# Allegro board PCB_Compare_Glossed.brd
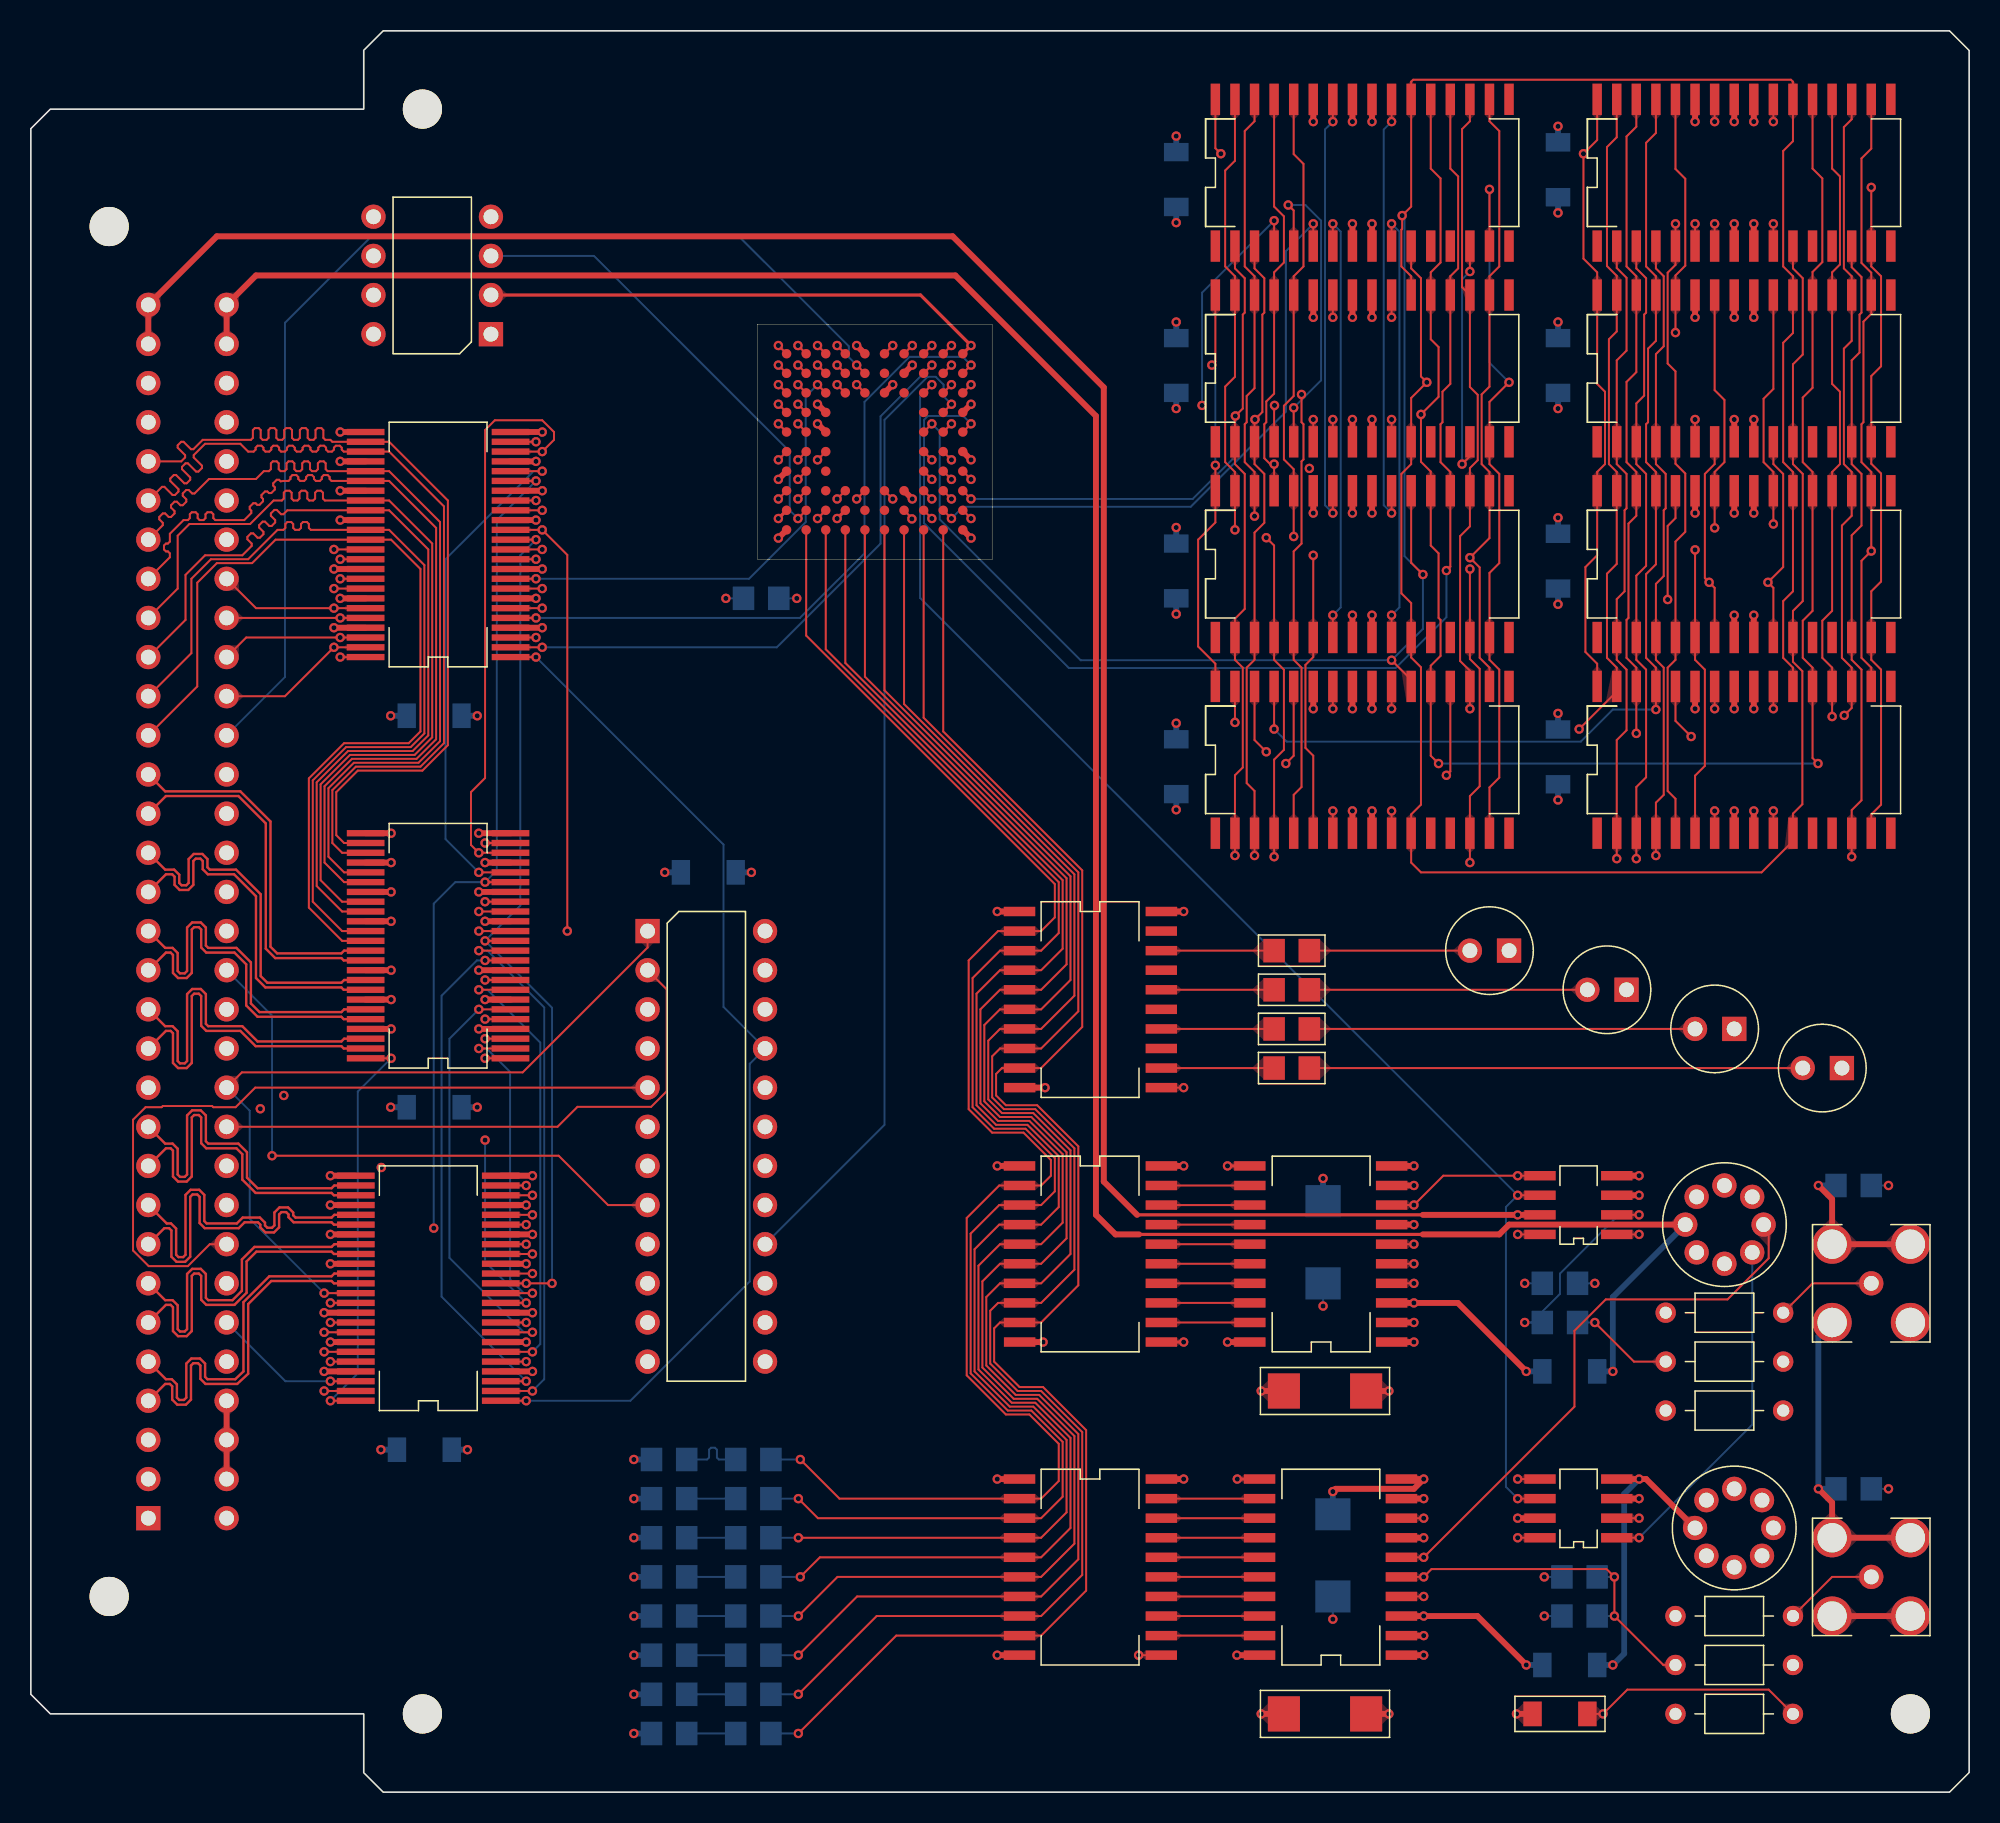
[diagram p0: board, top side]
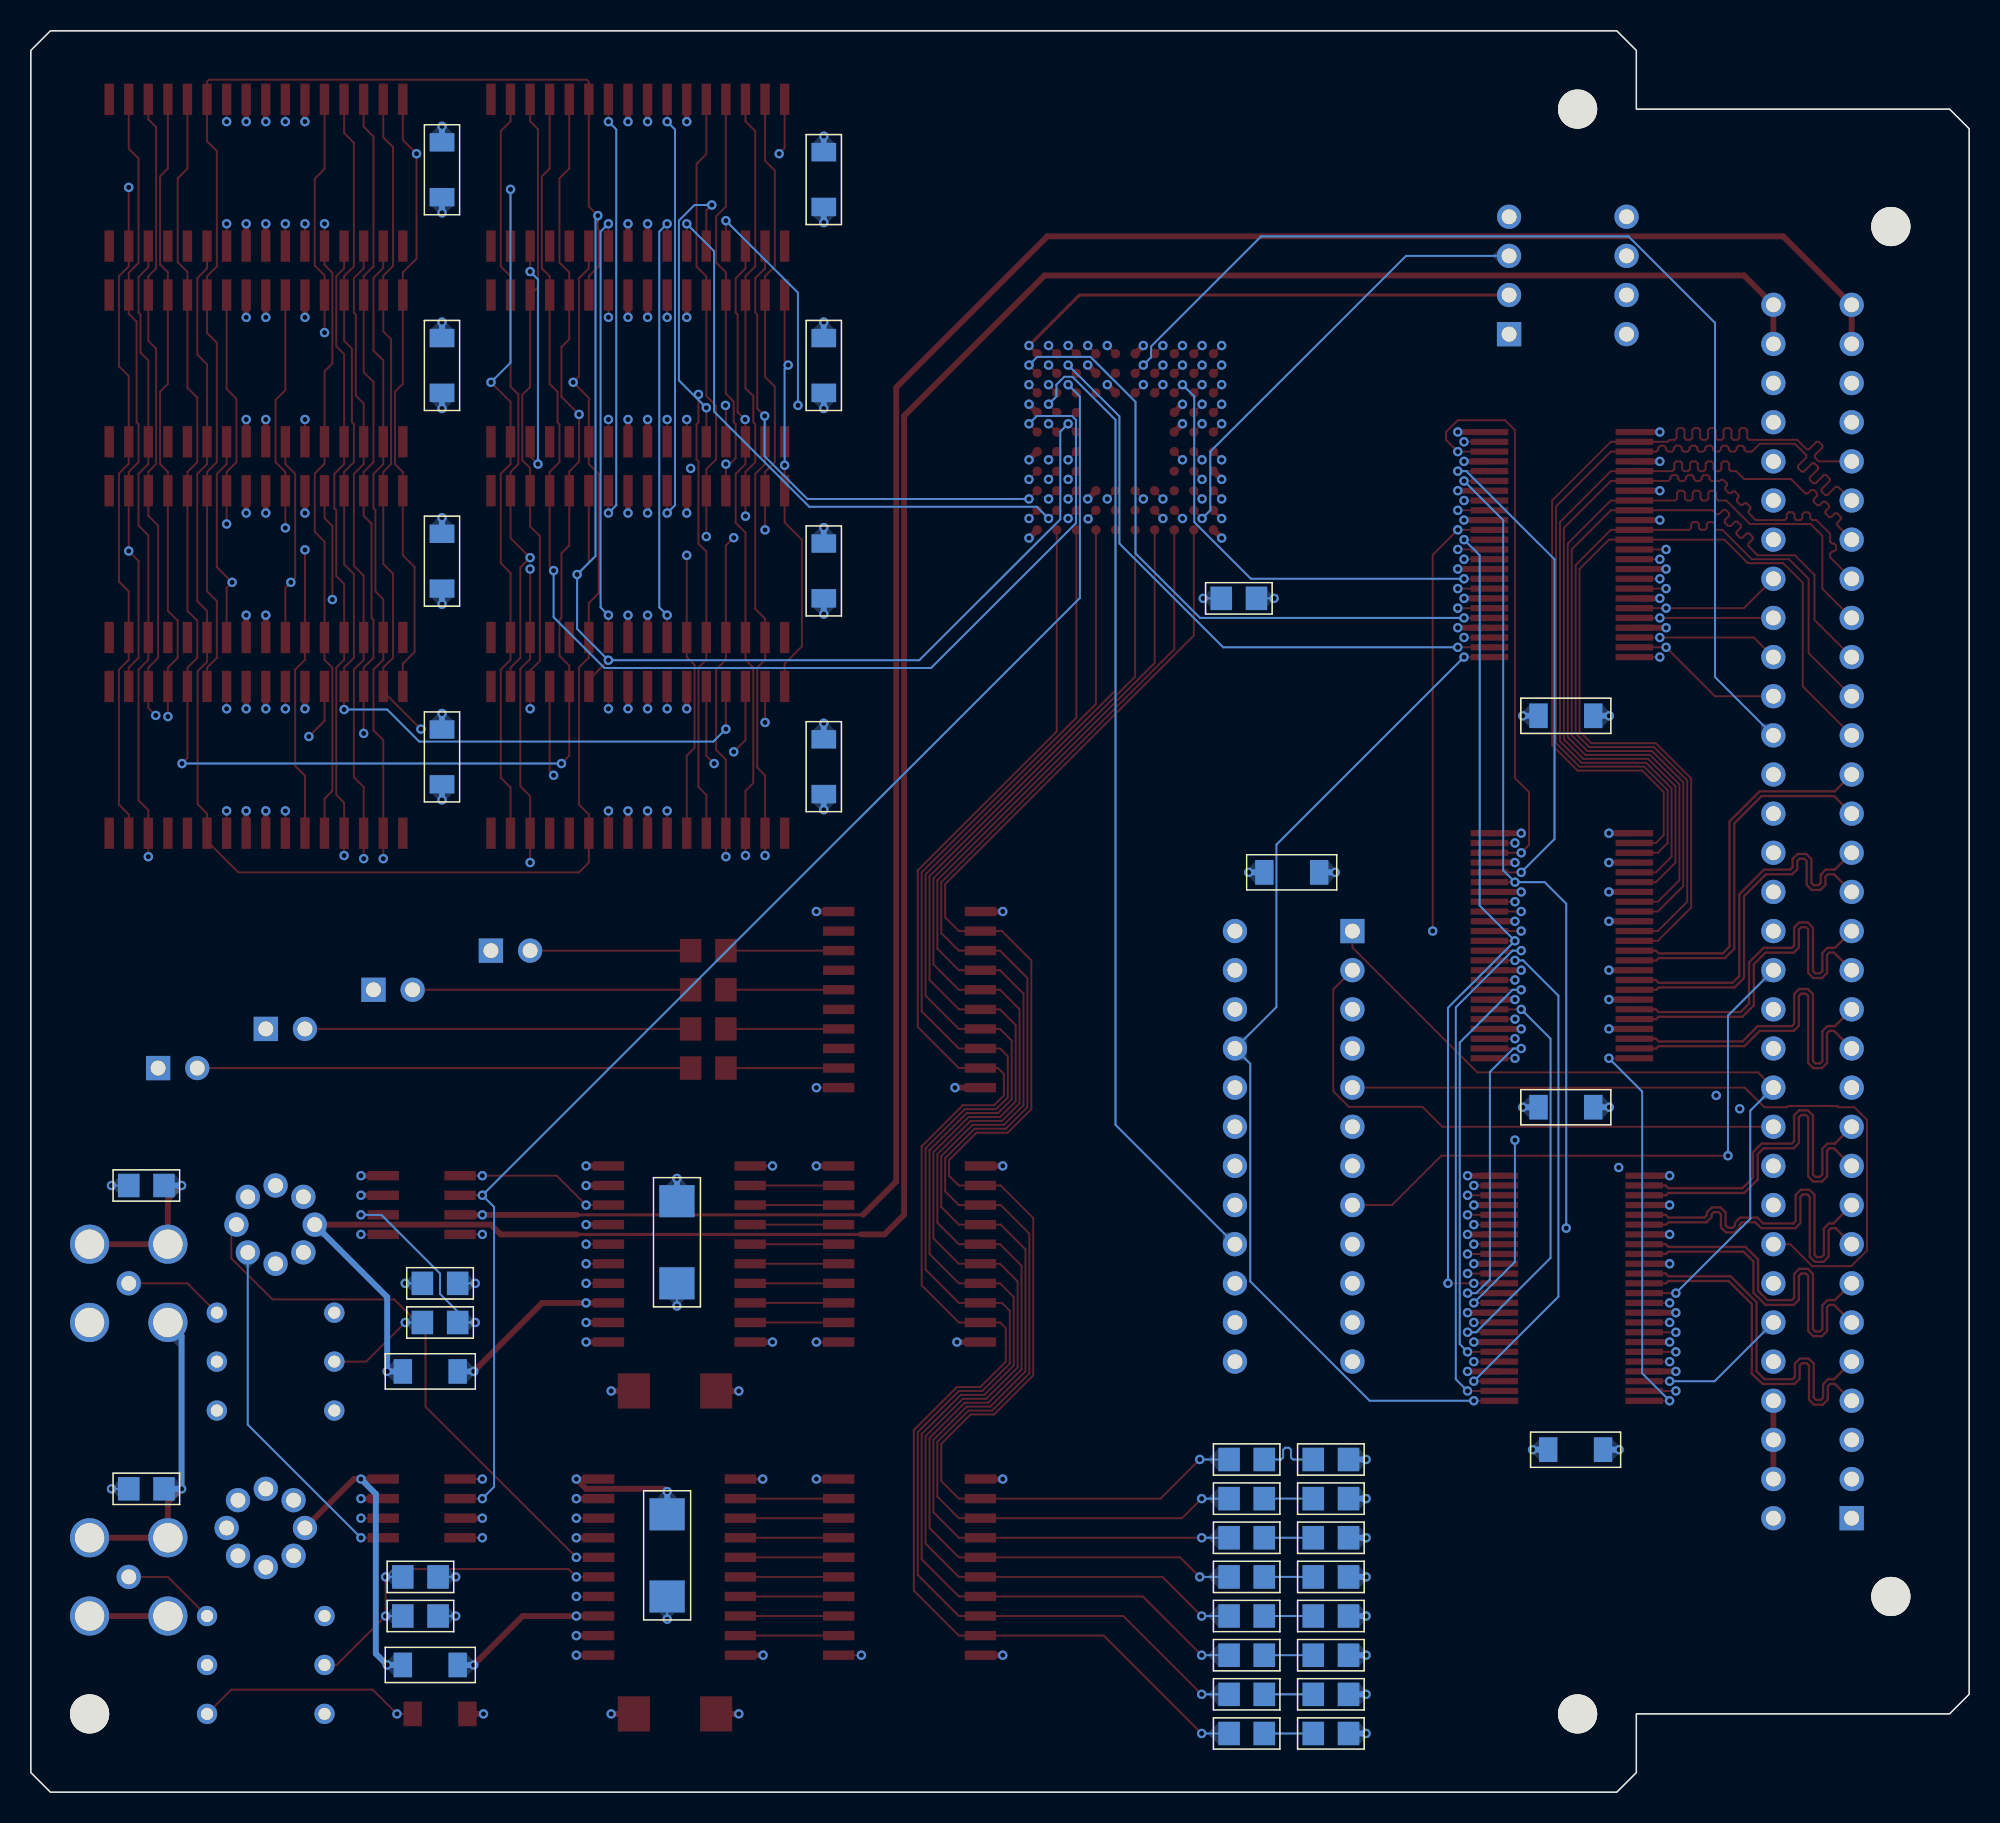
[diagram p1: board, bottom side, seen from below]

Outline 125.73 x 114.3 mm; copper layers: TOP, GND, INNER_1, INNER_2, VCC, BOTTOM. Coordinates in mm from the lower left corner of the outline.

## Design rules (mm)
constraint set DEFAULT: min track width 0.127
net group BNC2: nets BNC2 OUTA
net group BNC3: nets BNC3 OUTB
net group DC_NETS: nets AGND GND_EARTH
net group DP_A8_A9: nets A8 A9
net group DP_A10_A11: nets A10 A11
net group DP_A12_A13: nets A12 A13
net group DP_A14_A15: nets A14 A15
net group DP_D8_D9: nets D8 D9
net group DP_D10_D11: nets D10 D11
net group DP_D12_D13: nets D12 D13
net group DP_D14_D15: nets D14 D15
net group Q0: nets Q0 Q1
net group Q2: nets Q2 Q3
net group Q4: nets Q4 Q5
net group Q6: nets Q6 Q7
net group VCLKC: nets N409523 VCLKC
net group VD0: nets N14855 VD0
net group VD1: nets N14853 VD1
net group VD2: nets N14849 VD2
net group VD3: nets N14843 VD3
net group VD4: nets N15161 VD4
net group VD5: nets N15155 VD5
net group VD6: nets N15151 VD6
net group VD7: nets N15143 VD7
net group CLOCK: nets DCLK MCLK VCLKA
net group N00036: nets N00036 N282866 N282912
net group N00036_12287: nets N00036_12287 N282866_12286 N282912_12285
net group VREF: nets N00038 N00038_12290 VREF
nets with their own width: min track width 0.381; nets GND V12N V+12 VCC

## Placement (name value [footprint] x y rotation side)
C1  0.1uF  [SM_1206]  27.3 22.23 180 bottom
C2  0.1uF  [SM_1206]  27.94 44.45 180 bottom
C3  0.1uF  [SM_1206]  27.94 69.85 180 bottom
C4  0.1uF  [SM_1206]  45.72 59.69 180 bottom
C5  47PF  [SM_0805]  119.38 39.37 180 bottom
C6  47PF  [SM_0805]  119.38 19.69 180 bottom
C7  3300  [SM_0805]  42.55 6.35 180 bottom
C8  3300  [SM_0805]  42.55 11.43 180 bottom
C9  3300  [SM_0805]  42.55 16.51 180 bottom
C10  3300  [SM_0805]  42.55 21.59 180 bottom
C11  3300  [SM_0805]  42.55 3.81 180 bottom
C12  3300  [SM_0805]  42.55 8.89 180 bottom
C13  3300  [SM_0805]  42.55 13.97 180 bottom
C14  3300  [SM_0805]  42.55 19.05 180 bottom
C15  0.1uF  [SM_1206]  99.06 103.5 90 bottom
C16  0.1uF  [SM_1206]  99.06 78.11 90 bottom
C17  0.1uF  [SM_1206]  99.06 90.8 90 bottom
C18  0.1uF  [SM_1206]  74.3 102.87 90 bottom
C19  0.1uF  [SM_1206]  99.06 65.41 90 bottom
C20  0.1uF  [SM_1206]  74.3 90.8 90 bottom
C21  0.1uF  [SM_1206]  74.3 77.47 90 bottom
C22  0.1uF  [SM_1206]  74.3 64.77 90 bottom
C23  .01uF  [SMC_6032]  81.28 26.03 0 top
C24  .01uF  [SMC_6032]  83.82 33.02 90 bottom
C25  0.1uF  [SM_1206]  101.6 27.3 180 bottom
C26  .01uF  [SMC_6032]  81.28 5.08 0 top
C27  .01uF  [SMC_6032]  84.45 12.7 90 bottom
C28  0.1uF  [SM_1206]  101.6 8.25 180 bottom
D1  -  [LED]  95.88 54.61 180 top
D2  -  [LED]  103.5 52.07 180 top
D3  -  [LED]  110.49 49.53 180 top
D4  -  [LED]  117.47 46.99 180 top
J1  CON64  [DIN64]  7.62 17.78 0 top
J2  -  [BNC]  119.38 33.02 0 top
J3  -  [BNC]  119.38 13.97 0 top
L1  50  [IND300]  106.04 31.12 0 top
L2  50  [IND300]  106.68 11.43 0 top
L3  50  [IND300]  113.66 24.77 180 top
L4  50  [IND300]  113.66 27.94 180 top
L5  50  [IND300]  114.3 5.08 180 top
L6  50  [IND300]  114.3 8.25 180 top
NOREF  -  []  259.08 129.54 0 top
NOREF#2  -  []  -30.48 -55.88 0 top
NOREF#3  -  [unnamed#2]  25.4 5.08 0 top
R1  150  [SM_0805]  80.64 54.61 0 top
R2  150  [SM_0805]  80.64 52.07 0 top
R3  150  [SM_0805]  80.64 49.53 0 top
R4  150  [SM_0805]  80.64 46.99 0 top
R5  2K  [SM_0805]  48.51 77.47 180 bottom
R6  10K  [SM_0805]  45.72 6.35 0 bottom
R7  10K  [SM_0805]  45.72 11.43 0 bottom
R8  10K  [SM_0805]  45.72 16.51 0 bottom
R9  10K  [SM_0805]  45.72 21.59 0 bottom
R10  10K  [SM_0805]  45.72 3.81 0 bottom
R11  10K  [SM_0805]  45.72 8.89 0 bottom
R12  10K  [SM_0805]  45.72 13.97 0 bottom
R13  10K  [SM_0805]  45.72 19.05 0 bottom
R14  1/4w  [SM_1206]  100.97 5.08 180 top
R15  100  [SM_0805]  100.33 30.48 180 bottom
R16  100  [SM_0805]  100.33 33.02 180 bottom
R17  100  [SM_0805]  101.6 13.97 180 bottom
R18  100  [SM_0805]  101.6 11.43 180 bottom
U1  FCT16245  [SOIC48]  30.48 25.4 180 top
U2  20L10  [DIP24]  40 55.88 0 top
U3  FCT16245  [SOIC48]  31.11 47.62 180 top
U4  FCT16245  [SOIC48]  31.11 73.66 180 top
U5  EPF8282A_LCC  [BGA_84]  54.74 87.63 0 top
U6  74ACT574  [SOIC20]  64.13 57.15 0 top
U7  EPC1064  [DIP8]  29.84 94.61 180 top
U8  74ACT574  [SOIC20]  64.13 40.64 0 top
U9  74ACT574  [SOIC20]  64.13 20.32 0 top
U10  TC55B4257  [SOIC32]  76.84 62.23 90 top
U11  TC55B4257  [SOIC32]  101.6 100.33 90 top
U12  TC55B4257  [SOIC32]  101.6 62.23 90 top
U13  TC55B4257  [SOIC32]  76.84 87.63 90 top
U14  TC55B4257  [SOIC32]  76.84 74.93 90 top
U15  TC55B4257  [SOIC32]  76.84 100.33 90 top
U16  TC55B4257  [SOIC32]  101.6 74.93 90 top
U17  TC55B4257  [SOIC32]  101.6 87.63 90 top
U18  TLC5602A  [SOIC20]  88.27 29.21 180 top
U19  DG419AK  [SOIC8]  102.87 36.2 180 top
U20  TLE2037A  [TO-99]  110.49 17.14 0 top
U21  TLC5602A  [SOIC20]  88.9 8.89 180 top
U22  TLE2037A  [TO-99]  109.85 36.83 0 top
U23  DG419AK  [SOIC8]  102.87 16.51 180 top

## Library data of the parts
C1-C4 = CAP NP: signal model: DEFAULT_CAPACITOR_100000pF_2_1
C5 = CAP: signal model: DEFAULT_CAPACITOR_47pF_2_1; room: CHAN1
C6 = CAP: signal model: DEFAULT_CAPACITOR_47pF_2_1; room: CHAN2
C7-C14 = CAP: signal model: DEFAULT_RESISTOR_3300OHM_2_1
C15-C22 = CAP NP: signal model: DEFAULT_CAPACITOR_100000pF_2_1; room: MEM
C23 C24 = CAP: signal model: DEFAULT_CAPACITOR_10000pF_2_1; room: CHAN1
C25 = CAP NP: signal model: DEFAULT_CAPACITOR_100000pF_2_1; room: CHAN1
C26 C27 = CAP: signal model: DEFAULT_CAPACITOR_10000pF_2_1; room: CHAN2
C28 = CAP NP: signal model: DEFAULT_CAPACITOR_100000pF_2_1; room: CHAN2
D1-D4 = PHOTODIODE
J1 = CON64
J2 = BNC: alternate symbols: (bnc1); room: CHAN1
J3 = BNC: alternate symbols: (bnc1); room: CHAN2
L1 L3 L4 = INDUCTOR: signal model: DEFAULT_RESISTOR_50OHM_2_1; room: CHAN1
L2 L5 L6 = INDUCTOR: signal model: DEFAULT_RESISTOR_50OHM_2_1; room: CHAN2
R1-R4 = R: signal model: DEFAULT_RESISTOR_150OHM_2_1; room: LED
R5 = R: signal model: DEFAULT_RESISTOR_2000OHM_2_1
R6-R13 = R: signal model: DEFAULT_RESISTOR_10000OHM_2_1
R14 = R: signal model: DEFAULT_RESISTOR_0.25OHM_2_1; room: CHAN2
R15 R16 = R: signal model: DEFAULT_RESISTOR_100OHM_2_1; room: CHAN1
R17 R18 = R: signal model: DEFAULT_RESISTOR_100OHM_2_1; room: CHAN2
U1 U3 U4 = FCT16245
U2 = 20L10: alternate symbols: (T:SOIC24;B:SOIC24_PE)
U5 = EPF8282A/LCC_2
U6 = 74ACT574: room: LED
U7 = EPC1064
U8 = 74ACT574: room: CHAN1
U9 = 74ACT574: room: CHAN2
U10-U17 = TC55B4257: room: MEM
U18 = TLC5602A: room: CHAN1
U19 = DG419AK: room: CHAN1
U20 = TLE2037A: room: CHAN1
U21 = TLC5602A: room: CHAN2
U22 = TLE2037A: room: CHAN2
U23 = DG419AK: room: CHAN2

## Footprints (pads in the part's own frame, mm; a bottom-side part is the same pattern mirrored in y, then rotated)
BGA_84
  round 0.61 smd: A1(-5.715,5.715) A2(-4.445,5.715) A3(-3.175,5.715) A4(-1.905,5.715) A5(-0.635,5.715) A6(0.635,5.715) A7(1.905,5.715) A8(3.175,5.715) A9(4.445,5.715) A10(5.715,5.715) B1(-5.715,4.445) B2(-4.445,4.445) B3(-3.175,4.445) B4(-1.905,4.445) B5(-0.635,4.445) B6(0.635,4.445) B7(1.905,4.445) B8(3.175,4.445) B9(4.445,4.445) B10(5.715,4.445) C1(-5.715,3.175) C2(-4.445,3.175) C3(-3.175,3.175) C4(-1.905,3.175) C5(-0.635,3.175) C6(0.635,3.175) C7(1.905,3.175) C8(3.175,3.175) C9(4.445,3.175) C10(5.715,3.175) D1(-5.715,1.905) D2(-4.445,1.905) D3(-3.175,1.905) D8(3.175,1.905) D9(4.445,1.905) D10(5.715,1.905) E1(-5.715,0.635) E2(-4.445,0.635) E3(-3.175,0.635) E8(3.175,0.635) E9(4.445,0.635) E10(5.715,0.635) F1(-5.715,-0.635) F2(-4.445,-0.635) F3(-3.175,-0.635) F8(3.175,-0.635) F9(4.445,-0.635) F10(5.715,-0.635) G1(-5.715,-1.905) G2(-4.445,-1.905) G3(-3.175,-1.905) G8(3.175,-1.905) G9(4.445,-1.905) G10(5.715,-1.905) H1(-5.715,-3.175) H2(-4.445,-3.175) H3(-3.175,-3.175) H4(-1.905,-3.175) H5(-0.635,-3.175) H6(0.635,-3.175) H7(1.905,-3.175) H8(3.175,-3.175) H9(4.445,-3.175) H10(5.715,-3.175) J1(-5.715,-4.445) J2(-4.445,-4.445) J3(-3.175,-4.445) J4(-1.905,-4.445) J5(-0.635,-4.445) J6(0.635,-4.445) J7(1.905,-4.445) J8(3.175,-4.445) J9(4.445,-4.445) J10(5.715,-4.445) K1(-5.715,-5.715) K2(-4.445,-5.715) K3(-3.175,-5.715) K4(-1.905,-5.715) K5(-0.635,-5.715) K6(0.635,-5.715) K7(1.905,-5.715) K8(3.175,-5.715) K9(4.445,-5.715) K10(5.715,-5.715)
BNC
  round 1.575 hole 0.965: 1(0,0)
  round 2.54 hole 1.905: 2(-2.54,2.54) 3(-2.54,-2.54) 4(2.54,2.54) 5(2.54,-2.54)
DIN64
  round 2.54 hole 2.794 unplated: (-2.54,83.82) (-2.54,-5.08)
  rect 1.575x1.575 hole 0.965: 1(0,0)
  round 1.575 hole 0.965: 2(0,2.54) 3(0,5.08) 4(0,7.62) 5(0,10.16) 6(0,12.7) 7(0,15.24) 8(0,17.78) 9(0,20.32) 10(0,22.86) 11(0,25.4) 12(0,27.94) 13(0,30.48) 14(0,33.02) 15(0,35.56) 16(0,38.1) 17(0,40.64) 18(0,43.18) 19(0,45.72) 20(0,48.26) 21(0,50.8) 22(0,53.34) 23(0,55.88) 24(0,58.42) 25(0,60.96) 26(0,63.5) 27(0,66.04) 28(0,68.58) 29(0,71.12) 30(0,73.66) 31(0,76.2) 32(0,78.74) 33(5.08,0) 34(5.08,2.54) 35(5.08,5.08) 36(5.08,7.62) 37(5.08,10.16) 38(5.08,12.7) 39(5.08,15.24) 40(5.08,17.78) 41(5.08,20.32) 42(5.08,22.86) 43(5.08,25.4) 44(5.08,27.94) 45(5.08,30.48) 46(5.08,33.02) 47(5.08,35.56) 48(5.08,38.1) 49(5.08,40.64) 50(5.08,43.18) 51(5.08,45.72) 52(5.08,48.26) 53(5.08,50.8) 54(5.08,53.34) 55(5.08,55.88) 56(5.08,58.42) 57(5.08,60.96) 58(5.08,63.5) 59(5.08,66.04) 60(5.08,68.58) 61(5.08,71.12) 62(5.08,73.66) 63(5.08,76.2) 64(5.08,78.74)
DIP8
  rect 1.575x1.575 hole 0.965: 1(0,0)
  round 1.575 hole 0.965: 2(0,-2.54) 3(0,-5.08) 4(0,-7.62) 5(7.62,-7.62) 6(7.62,-5.08) 7(7.62,-2.54) 8(7.62,0)
DIP24
  rect 1.575x1.575 hole 0.965: 1(0,0)
  round 1.575 hole 0.965: 2(0,-2.54) 3(0,-5.08) 4(0,-7.62) 5(0,-10.16) 6(0,-12.7) 7(0,-15.24) 8(0,-17.78) 9(0,-20.32) 10(0,-22.86) 11(0,-25.4) 12(0,-27.94) 13(7.62,-27.94) 14(7.62,-25.4) 15(7.62,-22.86) 16(7.62,-20.32) 17(7.62,-17.78) 18(7.62,-15.24) 19(7.62,-12.7) 20(7.62,-10.16) 21(7.62,-7.62) 22(7.62,-5.08) 23(7.62,-2.54) 24(7.62,0)
IND300
  round 1.321 hole 0.787: 1(0,0) 2(7.62,0)
LED
  rect 1.575x1.575 hole 0.965: 1(0,0)
  round 1.575 hole 0.965: 2(2.54,0)
SM_0805
  rect 1.397x1.524 smd: 1(0,0) 2(2.286,0)
SM_1206
  rect 1.194x1.6 smd: 1(0,0) 2(3.556,0)
SMC_6032
  rect 2.083x2.286 smd: 1(0,0) 2(5.334,0)
SOIC8
  rect 2.032x0.61 smd: 1(0,0) 2(0,-1.27) 3(0,-2.54) 4(0,-3.81) 5(4.978,-3.81) 6(4.978,-2.54) 7(4.978,-1.27) 8(4.978,0)
SOIC20
  rect 2.032x0.61 smd: 1(0,0) 2(0,-1.27) 3(0,-2.54) 4(0,-3.81) 5(0,-5.08) 6(0,-6.35) 7(0,-7.62) 8(0,-8.89) 9(0,-10.16) 10(0,-11.43) 11(9.195,-11.43) 12(9.195,-10.16) 13(9.195,-8.89) 14(9.195,-7.62) 15(9.195,-6.35) 16(9.195,-5.08) 17(9.195,-3.81) 18(9.195,-2.54) 19(9.195,-1.27) 20(9.195,0)
SOIC32
  rect 2.032x0.61 smd: 1(0,0) 2(0,-1.27) 3(0,-2.54) 4(0,-3.81) 5(0,-5.08) 6(0,-6.35) 7(0,-7.62) 8(0,-8.89) 9(0,-10.16) 10(0,-11.43) 11(0,-12.7) 12(0,-13.97) 13(0,-15.24) 14(0,-16.51) 15(0,-17.78) 16(0,-19.05) 17(9.525,-19.05) 18(9.525,-17.78) 19(9.525,-16.51) 20(9.525,-15.24) 21(9.525,-13.97) 22(9.525,-12.7) 23(9.525,-11.43) 24(9.525,-10.16) 25(9.525,-8.89) 26(9.525,-7.62) 27(9.525,-6.35) 28(9.525,-5.08) 29(9.525,-3.81) 30(9.525,-2.54) 31(9.525,-1.27) 32(9.525,0)
SOIC48
  rect 2.438x0.406 smd: 1(0,0) 2(0,-0.635) 3(0,-1.27) 4(0,-1.905) 5(0,-2.54) 6(0,-3.175) 7(0,-3.81) 8(0,-4.445) 9(0,-5.08) 10(0,-5.715) 11(0,-6.35) 12(0,-6.985) 13(0,-7.62) 14(0,-8.255) 15(0,-8.89) 16(0,-9.525) 17(0,-10.16) 18(0,-10.795) 19(0,-11.43) 20(0,-12.065) 21(0,-12.7) 22(0,-13.335) 23(0,-13.97) 24(0,-14.605) 25(9.398,-14.605) 26(9.398,-13.97) 27(9.398,-13.335) 28(9.398,-12.7) 29(9.398,-12.065) 30(9.398,-11.43) 31(9.398,-10.795) 32(9.398,-10.16) 33(9.398,-9.525) 34(9.398,-8.89) 35(9.398,-8.255) 36(9.398,-7.62) 37(9.398,-6.985) 38(9.398,-6.35) 39(9.398,-5.715) 40(9.398,-5.08) 41(9.398,-4.445) 42(9.398,-3.81) 43(9.398,-3.175) 44(9.398,-2.54) 45(9.398,-1.905) 46(9.398,-1.27) 47(9.398,-0.635) 48(9.398,0)
TO-99
  round 1.575 hole 0.965: 1(0,-2.54) 2(1.803,-1.803) 3(2.54,0) 4(1.803,1.803) 5(0,2.54) 6(-1.803,1.803) 7(-2.54,0) 8(-1.803,-1.803)
unnamed#2
  round 2.54 hole 2.794 unplated: (0,104.14) (0,0) (96.52,0)

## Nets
AGND: C24.2 C25.2 C27.2 C28.2 J1.34 J1.35 J1.36 U18.3 U18.7 U18.10 U19.3 U21.3 U21.7 U21.10 U23.3
GND: C1.2 C2.2 C3.2 C4.2 C7.2 C8.2 C9.2 C10.2 C11.2 C12.2 C13.2 C14.2 C15.2 C16.2 C17.2 C18.2 C19.2 C20.2 C21.2 C22.2 C23.2 C26.2 J1.1 J1.2 J1.3 J1.33 R14.2 U1.4 U1.10 U1.15 U1.21 U1.24 U1.25(G\) U1.28 U1.34 U1.39 U1.45 U2.11 U2.12 U2.13 U3.4 U3.10 U3.15 U3.21 U3.24 U3.25(G\) U3.28 U3.34 U3.39 U3.45 U4.4 U4.10 U4.15 U4.21 U4.24 U4.25(G\) U4.28 U4.34 U4.39 U4.45 U5.A5 U5.C6 U5.D3 U5.D10 U5.E3 U5.F10 U5.K10 U6.1 U6.10 U7.5 U8.1 U8.10 U9.1 U9.10 U10.9 U10.25 U10.27 U11.9 U11.25 U11.27 U12.9 U12.25 U12.27 U13.9 U13.25 U13.27 U14.9 U14.25 U14.27 U15.9 U15.25 U15.27 U16.9 U16.25 U16.27 U17.9 U17.25 U17.27 U18.1 U18.20 U21.1 U21.20
GND_EARTH: C5.2 C6.2 J2.2 J2.3 J2.4 J2.5(GND5) J3.2 J3.3 J3.4 J3.5(GND5)
V12N: J1.31 J1.32 U19.7 U20.4(V-) U22.4(V-) U23.7
VCC: C1.1 C2.1 C3.1 C4.1 C15.1 C16.1 C17.1 C18.1 C19.1 C20.1 C21.1 C22.1 C23.1 C26.1 D1.1 D2.1 D3.1 D4.1 J1.29 J1.30 J1.62 L4.1 L6.1 U1.7 U1.18 U1.31 U1.42 U2.24(VCC) U3.7 U3.18 U3.31 U3.42 U4.7 U4.18 U4.31 U4.42 U5.B7 U5.G1 U5.H7 U5.K1 U6.20 U7.7 U7.8 U8.20 U9.20 U10.8 U10.24 U11.8 U11.24 U12.8 U12.24 U13.8 U13.24 U14.8 U14.24 U15.8 U15.24 U16.8 U16.24 U17.8 U17.24 U18.2 U18.9(VD2) U21.2 U21.9(VD2)
A0: J1.54 U4.47
A1: J1.55 U4.46
A2: J1.56 U4.44
A3: J1.57 U4.43
A4: J1.58 U4.41
A5: J1.59 U4.40
A6: J1.60 U4.38
A7: J1.61 U4.37
A8: J1.13 U3.47
A9: J1.14 U3.46
A10: J1.15 U3.44
A11: J1.16 U3.43
A12: J1.17 U3.41
A13: J1.18 U3.40
A14: J1.19 U3.38
A15: J1.20 U3.37
A16: J1.37 U1.47
A17: J1.38 U1.46
A18: J1.39 U1.44 U2.6
A19: J1.40 U1.43 U2.5
A20: J1.41 U1.41 U2.4
A21: J1.42 U1.40 U2.3
A22: J1.43 U1.38 U2.2
A23: J1.44 U1.37 U2.1
AEN: J1.47 U2.8
BA0: U1.13 U3.13 U4.13 U5.A6
BA1: U1.14 U3.14 U4.14 U5.A7
BA2: U1.16 U3.16 U4.16 U5.A8
BA3: U1.17 U3.17 U4.17 U5.A9
BA4: U1.19 U3.19 U4.19
BA5: U1.20 U3.20 U4.20
BA6: U1.22 U3.22 U4.22
BA7: U1.23 U3.23 U4.23
BD0: U4.12 U5.C5
BD1: U4.11 U5.C4
BD2: U4.9 U5.C3
BD3: U4.8 U5.C2
BD4: U4.6 U5.C1
BD5: U4.5 U5.B10
BD6: U4.3 U5.B9
BD7: U4.2 U5.B8
BD8: U1.12 U3.2
BD9: U1.11 U3.3
BD10: U1.9 U3.5
BD11: U1.8 U3.6
BD12: U1.6 U3.8
BD13: U1.5 U3.9
BD14: U1.3 U3.11
BD15: U1.2 U3.12
BNC2: C5.1 J2.1 L1.2
BNC3: C6.1 J3.1 L2.2
BRD: U2.16 U5.D9
BRESET: U2.15 U5.B2
BWR: U2.17 U5.H2
D0: J1.28 U3.26 U4.26
D1: J1.27 U3.27 U4.27
D2: J1.26 U3.29 U4.29
D3: J1.25 U3.30 U4.30
D4: J1.24 U3.32 U4.32
D5: J1.23 U3.33 U4.33
D6: J1.22 U3.35 U4.35
D7: J1.21 U3.36 U4.36
D8: J1.4 U1.36
D9: J1.5 U1.35
D10: J1.6 U1.33
D11: J1.7 U1.32
D12: J1.8 U1.30
D13: J1.9 U1.29
D14: J1.10 U1.27
D15: J1.11 U1.26
DATA: U5.B4 U7.1
DCLK: U5.A10 U7.2
DDIR: U1.48 U2.20 U3.48 U4.48
DEN: U1.1 U2.21 U4.1
DHEN: U2.22 U3.1
FPGA: U2.18 U5.C10
GAIN: U5.C8 U19.6 U23.6
HS: U2.19 U5.C9
MCLK: J1.52 U5.J1
MRD: J1.46 U2.9
MWR: J1.45 U2.10
N00036_12287: L6.2 R17.1 R18.1 U21.5 U21.8 U23.5(VL)
N00038_12290: C27.1 L5.2 U21.4
N00044_12288: U22.2 U23.1
N00060_12289: U21.6 U22.3
N282866_12286: R17.2 U23.8
N282912_12285: R18.2 U23.2
NCS: U5.B1 U7.4
OE: U5.J2 U7.3(OE)
OUTA: L1.1 U20.6
OUTB: L2.1 U22.6
Q0: R4.1 U6.12(Q8)
Q1: D4.2(CATHODE) R4.2
Q2: R3.1 U6.14
Q3: D3.2(CATHODE) R3.2
Q4: R2.1 U6.16
Q5: D2.2(CATHODE) R2.2
Q6: R1.1 U6.18
Q7: D1.2(CATHODE) R1.2
RA0: U5.H6 U10.5 U11.5 U12.5 U13.5 U14.5 U15.5 U16.5 U17.5
RA1: U5.H8 U10.4 U11.4 U12.4 U13.4 U14.4 U15.4 U16.4 U17.4
RA2: U5.H9 U10.3 U11.3 U12.3 U13.3 U14.3 U15.3 U16.3 U17.3
RA3: U5.H10 U10.2 U11.2 U12.2 U13.2 U14.2 U15.2 U16.2 U17.2
RA4: U5.G8 U10.32 U11.32 U12.32 U13.32 U14.32 U15.32 U16.32 U17.32
RA5: U5.G9 U10.31 U11.31 U12.31 U13.31 U14.31 U15.31 U16.31 U17.31
RA6: U5.G10 U10.30 U11.30 U12.30 U13.30 U14.30 U15.30 U16.30 U17.30
RA7: U5.F8 U10.29 U11.29 U12.29 U13.29 U14.29 U15.29 U16.29 U17.29
RA8: U5.F9 U10.28 U11.28 U12.28 U13.28 U14.28 U15.28 U16.28 U17.28
RA9: U5.E8 U10.22 U11.22 U12.22 U13.22 U14.22 U15.22 U16.22 U17.22
RA10: U5.E9 U10.21 U11.21 U12.21 U13.21 U14.21 U15.21 U16.21 U17.21
RA11: U5.E10 U10.20 U11.20 U12.20 U13.20 U14.20 U15.20 U16.20 U17.20
RA12: U5.G2 U10.19 U11.19 U12.19 U13.19 U14.19 U15.19 U16.19 U17.19
RA13: U5.F2 U10.18 U11.18 U12.18 U13.18 U14.18 U15.18 U16.18 U17.18
RA14: U5.E2 U10.15 U11.15 U12.15 U13.15 U14.15 U15.15 U16.15 U17.15
RA15: U5.D2 U10.14 U11.14 U12.14 U13.14 U14.14 U15.14 U16.14 U17.14
RCS0: U5.J8 U10.6 U14.6
RCS1: U5.J9 U11.6 U15.6
RCS2: U5.J10 U12.6 U16.6
RCS3: U5.F3 U13.6 U17.6
RD0: U5.F1 U14.26 U15.26 U16.26 U17.26
RD1: U5.E1 U14.23 U15.23 U16.23 U17.23
RD2: U5.D1 U14.10 U15.10 U16.10 U17.10
RD3: U5.H1 U14.7 U15.7 U16.7 U17.7
RD4: U5.A1 U10.26 U11.26 U12.26 U13.26
RD5: U5.A2 U10.23 U11.23 U12.23 U13.23
RD6: U5.A3 U10.10 U11.10 U12.10 U13.10
RD7: U5.A4 U10.7 U11.7 U12.7 U13.7
RDY: J1.50 U2.23
RESET: J1.53 U5.B5
RWE: U5.H5 U10.11(W\E\) U11.11(W\E\) U12.11(W\E\) U13.11(W\E\) U14.11(W\E\) U15.11(W\E\) U16.11(W\E\) U17.11(W\E\)
SEL: U2.14 U5.B3
V+12: C25.1 C28.1 J1.63 J1.64 U19.4 U20.7 U22.7 U23.4
VCLKA: U5.J4 U8.11 U18.11 U21.11
VCLKC: R5.2 U9.11
VD0: R9.2 U5.K2 U6.2 U8.2 U9.2
VD1: R13.2 U5.K3 U6.3 U8.3 U9.3
VD2: R8.2 U5.K4 U6.4 U8.4 U9.4
VD3: R12.2 U5.K5 U6.5 U8.5 U9.5
VD4: R7.2 U5.K6 U6.6 U8.6 U9.6
VD5: R11.2 U5.K7 U6.7 U8.7 U9.7
VD6: R6.2 U5.K8 U6.8 U8.8 U9.8
VD7: R10.2 U5.K9(VD7) U6.9 U8.9 U9.9
VREF: L3.1 L5.1 R14.1
WAIT: J1.51 U5.J3
WSTAT: U5.H4 U6.11
N00036: L4.2 R15.1 R16.1 U18.5 U18.8 U19.5(VL)
N00038: C24.1 L3.2 U18.4
N00044: U19.1 U20.2
N00060: U18.6 U20.3
N14843: C13.1 R12.1
N14849: C9.1 R8.1
N14853: C14.1 R13.1
N14855: C10.1 R9.1
N15143: C11.1 R10.1
N15151: C7.1 R6.1
N15155: C12.1 R11.1
N15161: C8.1 R7.1
N58063: U8.19 U18.12
N58118: U8.18 U18.13
N58173: U8.17 U18.14
N58228: U8.16 U18.15
N58283: U8.15 U18.16
N58338: U8.14 U18.17
N58393: U8.13 U18.18
N58448: U8.12(Q8) U18.19
N58834: U9.19 U21.12
N58889: U9.18 U21.13
N58944: U9.17 U21.14
N58999: U9.16 U21.15
N59054: U9.15 U21.16
N59109: U9.14 U21.17
N59164: U9.13 U21.18
N59219: U9.12(Q8) U21.19
N282866: R16.2 U19.8
N282912: R15.2 U19.2
N409523: R5.1 U5.J7

Pads without a net: J1 12 48 49; U2 7; U5 B6 C7 D8 G3 H3 J5 J6; U6 13 15 17 19; U7 6; U10 1 12 13 16 17; U11 1 12 13 16 17; U12 1 12 13 16 17; U13 1 12 13 16 17; U14 1 12 13 16 17; U15 1 12 13 16 17; U16 1 12 13 16 17; U17 1 12 13 16 17; U20 1 5 8; U22 1 5 8

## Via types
v1: diameter 0.61, hole 0.33, TOP to BOTTOM, 440 vias

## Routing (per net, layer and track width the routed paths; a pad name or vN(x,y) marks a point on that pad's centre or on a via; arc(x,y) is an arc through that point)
AGND: length 183.5
  TOP w0.381: v1(84.45,19.51) 84.63,19.69 89.71,19.69 v1(90.35,20.32) U21.10 ; U23.3 v1(104.32,19.05) ; J1.34 J1.35 J1.36 ; v1(97,27.3) 92.56,31.75 v1(89.71,31.75) U18.3 ; U19.3 v1(104.32,38.73) ; U18.10 v1(89.71,40.64) ; U18.7 v1(89.71,36.83) ; U21.7 v1(90.35,16.51) ; v1(97,8.25) 93.83,11.43 v1(90.35,11.43) U21.3
  INNER_1 w0.381: v1(104.32,19.05) 97,26.37 v1(97,27.3) ; v1(90.35,11.43) 89.2,12.57 89.2,15.37 v1(90.35,16.51) 89.71,17.14 89.71,19.69 v1(90.35,20.32) 90.35,31.12 v1(89.71,31.75) 88.57,32.89 88.57,35.69 v1(89.71,36.83) 89.08,37.46 89.08,40 v1(89.71,40.64)
  INNER_2 w0.381: v1(84.45,19.51) 81.1,22.86 J1.35 ; v1(104.32,38.73) 102.41,36.83 v1(89.71,36.83) ; v1(89.71,40.64) 84.63,40.64 v1(83.82,39.83)
  BOTTOM w0.381: C24.2 v1(83.82,39.83) ; C25.2 v1(97,27.3) ; C27.2 v1(84.45,19.51) ; C28.2 v1(97,8.25)
GND: length 135.3
  TOP w0.381: U6.1 v1(62.69,57.15) ; 21.72,56.52 v1(23.37,56.52) ; U5.E3 v1(51.03,88.8) ; U1.10 v1(32.54,31.12) ; U17.25 v1(110.49,95.71) ; U5.K10 v1(60.99,81.38) ; U3.24 v1(29.06,62.23) ; U12.27 v1(107.95,70.31) ; U3.15 v1(29.46,56.52) ; 83.19,71.75 v1(83.19,70.31) ; U21.20 v1(78.23,8.89) ; U8.1 v1(62.69,40.64) ; 31.11,60.32 v1(29.46,60.32) ; U1.15 v1(32.13,34.29) ; U13.9 v1(87,89.08) ; U6.10 v1(65.79,45.72) ; U18.1 v1(89.71,29.21) ; 21.72,82.55 v1(20.07,82.55) ; 21.72,75.56 v1(19.66,75.56) ; U5.C6 v1(55.91,91.34) ; U11.25 v1(110.49,108.41) ; U4.15 v1(32.77,82.55) ; U12.9 v1(111.76,63.68) ; U4.24 v1(33.17,88.27) ; 21.72,49.53 v1(23.37,49.53) ; U8.10 v1(65.66,29.21) ; 83.19,84.45 v1(83.19,83.01) ; C23.2 v1(88.09,26.03) ; U5.D3 v1(51.03,90.07) ; U1.4 v1(32.54,27.3) ; U1.25 v1(19.43,40) ; U15.25 v1(85.72,108.41) ; U18.20 v1(77.62,29.21) ; U21.1 v1(90.35,8.89) ; U13.25 v1(85.72,95.71) ; U14.25 v1(85.72,83.01) ; U12.25 v1(110.49,70.31) ; U3.4 v1(29.06,49.53) ; U1.24 v1(32.54,40) ; U1.45 v1(19.02,27.3) ; 21.72,60.32 v1(23.37,60.32) ; 21.72,86.36 v1(20.07,86.36) ; U5.A5 v1(53.57,93.88) ; 83.19,97.16 v1(83.19,95.71) ; U4.21 v1(32.77,86.36) ; 21.72,53.34 v1(23.37,53.34) ; 83.19,109.86 v1(83.19,108.41) ; U1.21 v1(32.13,38.1) ; U1.34 v1(19.43,34.29) ; U9.10 v1(62.69,8.89) ; U16.25 v1(110.49,83.01) ; U1.28 v1(19.43,38.1) ; U9.1 v1(62.69,20.32) ; U15.9 v1(87,101.78) ; C26.2 v1(88.09,5.08) ; U10.25 v1(85.72,70.31) ; U16.27 v1(107.95,83.01) ; U4.4 v1(33.17,75.56) ; R14.2 v1(96.37,5.08) ; 21.72,79.38 v1(19.66,79.38) ; U17.9 v1(111.76,89.08) ; 21.72,88.27 v1(20.07,88.27) ; U5.D10 v1(60.99,90.07) ; U16.9 v1(111.76,76.38) ; U11.27 v1(107.95,108.41) ; U4.10 v1(33.17,79.38) ; U10.9 v1(87,63.68) ; 60.45,87 v1(60.99,86.46) ; U11.9 v1(111.76,101.78) ; U1.39 v1(19.02,31.12) ; U17.27 v1(107.95,95.71) ; 21.72,62.23 v1(23.37,62.23) ; U3.10 v1(29.06,53.34) ; U14.9 v1(87,76.38)
  BOTTOM w0.381: C3.2 v1(23.34,69.85) ; C18.2 v1(74.3,107.47) ; C17.2 v1(99.06,95.4) ; C12.2 v1(39.12,8.89) ; C2.2 v1(23.34,44.45) ; C15.2 v1(99.06,108.1) ; C1.2 v1(22.71,22.23) ; C10.2 v1(39.12,21.59) ; C21.2 v1(74.3,82.07) ; C20.2 v1(74.3,95.4) ; C7.2 v1(39.12,6.35) ; C9.2 v1(39.12,16.51) ; C11.2 v1(39.12,3.81) ; C14.2 v1(39.12,19.05) ; C8.2 v1(39.12,11.43) ; C22.2 v1(74.3,69.37) ; C16.2 v1(99.06,82.7) ; C4.2 v1(41.12,59.69) ; C13.2 v1(39.12,13.97) ; C19.2 v1(99.06,70)
  vias: v1(14.88,44.35) v1(16.41,45.21) v1(22.73,40.54)
GND_EARTH: length 51.7
  TOP w0.381: J3.5 J3.3 ; J2.4 J2.2 116.84,38.48 v1(115.95,39.37) ; J3.4 J3.2 116.84,18.8 v1(115.95,19.69)
  INNER_1 w0.381: J3.2 J3.3 ; J2.3 J2.2 ; J2.5 J2.4
  BOTTOM w0.381: J2.3 115.95,29.59 v1(115.95,19.69) C6.2 ; C5.2 v1(115.95,39.37)
V12N: length 210.5
  TOP w0.203: 71.75,37.46 90.3,37.46
  TOP w0.381: 90.3,37.46 v1(96.44,37.46) U19.7 ; 71.75,37.46 69.6,39.62 69.6,91.16 59.79,100.97 12.06,100.97 J1.32 J1.31 ; U23.7 v1(96.44,17.78)
  INNER_1 w0.381: v1(96.44,17.78) 95.3,18.92 95.3,36.32 v1(96.44,37.46)
  INNER_2 w0.381: v1(96.44,17.78) 97.08,18.41 105.28,18.41 107.67,20.8 111.89,20.8 112.29,20.4 U20.4 ; v1(96.44,37.46) 100.13,41.15 110.52,41.15 111.66,40 U22.4
VCC: length 72.5
  TOP w0.381: U3.7 v1(29.46,51.43) ; C26.1 v1(79.81,5.08) ; U5.K1 v1(48.49,81.38) ; 21.72,84.45 v1(20.07,84.45) ; U5.G1 v1(48.49,85.19) ; U1.7 v1(32.13,29.21) ; C23.1 v1(79.81,26.03) ; U1.18 v1(32.54,36.2) ; U17.24 v1(111.76,95.71) ; U4.18 v1(33.17,84.45) ; U12.8 v1(110.49,63.68) ; U5.H7 v1(57.18,83.92) ; U15.24 v1(87,108.41) ; 21.72,58.42 v1(23.37,58.42) ; U14.8 v1(85.72,76.38) ; U11.24 v1(111.76,108.41) ; U5.B7 v1(57.18,92.61) ; U11.8 v1(110.49,101.78) ; U9.20 v1(74.78,20.32) ; U12.24 v1(111.76,70.31) ; U10.24 v1(87,70.31) ; U21.9 v1(90.35,19.05) ; U13.24 v1(87,95.71) ; U6.20 v1(74.78,57.15) ; U3.18 v1(29.06,58.42) ; U1.42 v1(19.43,29.21) ; 21.72,77.47 v1(20.07,77.47) ; U16.8 v1(110.49,76.38) ; U18.9 v1(89.71,39.37) ; U16.24 v1(111.76,83.01) ; U15.8 v1(85.72,101.78) ; U14.24 v1(87,83.01) ; U1.31 v1(19.43,36.2) ; U18.2 v1(89.71,30.48) ; U21.2 v1(90.35,10.16) ; U13.8 v1(85.72,89.08) ; U4.7 v1(32.77,77.47) ; 21.72,51.43 v1(23.37,51.43) ; U10.8 v1(85.72,63.68) ; U17.8 v1(110.49,89.08) ; U8.20 v1(74.78,40.64)
  BOTTOM w0.381: C15.1 v1(99.06,102.49) ; C19.1 v1(99.06,64.39) ; C16.1 v1(99.06,77.09) ; C18.1 v1(74.3,101.85) ; C4.1 v1(46.74,59.69) ; C2.1 v1(28.96,44.45) ; C21.1 v1(74.3,76.45) ; C17.1 v1(99.06,89.79) ; C1.1 v1(28.32,22.23) ; C20.1 v1(74.3,89.79) ; C3.1 v1(28.96,69.85) ; C22.1 v1(74.3,63.75)
A0: length 10.3
  TOP w0.127: U4.47 v1(19.66,74.3) 16.48,71.12 J1.54
A1: length 9.5
  TOP w0.127: U4.46 v1(20.07,74.93) 13.97,74.93 J1.55
A2: length 9
  TOP w0.127: 21.72,76.2 v1(20.07,76.2) J1.56
A3: length 9.8
  TOP w0.127: J1.57 14.6,76.83 v1(19.66,76.83) 21.72,76.83
A4: length 10.3
  TOP w0.127: 21.72,78.11 v1(19.66,78.11)
  INNER_2 w0.127: J1.58 16.48,81.28 v1(19.66,78.11)
A5: length 13.1
  TOP w0.127: 21.72,78.74 v1(20.07,78.74)
  INNER_2 w0.127: v1(20.07,78.74) 20.83,79.5 20.83,80.26 17.27,83.82 J1.59
A6: length 16.5
  TOP w0.127: 21.72,80.01 v1(20.07,80.01)
  INNER_1 w0.127: J1.60 11.46,85.12 11.46,81.03 12.47,80.01 v1(20.07,80.01)
A7: length 13.2
  TOP w0.127: 21.72,80.64 v1(19.66,80.64)
  INNER_1 w0.127: v1(19.66,80.64) 19.66,81.94 J1.61
A8: length 23.8
  TOP w0.152: U3.47 20.29,48.26 20.14,48.41 14.58,48.41 13.59,49.4 11.38,49.4 11.05,49.73 11.05,51.66 10.9,51.82 10.59,51.82 10.44,51.66 10.44,47.32 10.11,46.99 9.55,46.99 9.22,47.32 9.22,49.25 9.07,49.4 8.76,49.4 J1.13
A9: length 23.8
  TOP w0.152: J1.14 8.71,49.71 9.19,49.71 9.52,49.38 9.52,47.45 9.68,47.29 9.98,47.29 10.13,47.45 10.13,51.79 10.46,52.12 11.02,52.12 11.35,51.79 11.35,49.86 11.51,49.71 13.72,49.71 14.71,48.72 20.14,48.72 20.32,48.89 U3.46
A10: length 23.7
  TOP w0.152: 21.72,50.16 20.29,50.16 20.14,50.32 14.71,50.32 13.97,51.05 13.97,53.72 13.21,54.48 11.38,54.48 11.05,54.81 11.05,55.98 10.9,56.13 10.59,56.13 10.44,55.98 10.44,53.16 10.11,52.83 9.55,52.83 9.22,53.16 9.22,54.33 9.07,54.48 8.76,54.48 J1.15
A11: length 23.7
  TOP w0.152: J1.16 8.71,54.79 9.19,54.79 9.52,54.46 9.52,53.29 9.68,53.14 9.98,53.14 10.13,53.29 10.13,56.11 10.46,56.44 11.02,56.44 11.35,56.11 11.35,54.94 11.51,54.79 13.33,54.79 14.27,53.85 14.27,51.18 14.83,50.62 20.14,50.62 20.32,50.8 21.72,50.8
A12: length 24
  TOP w0.152: 21.72,52.07 20.29,52.07 20.14,52.22 15.21,52.22 14.6,52.83 14.6,58.14 13.18,59.56 11.48,59.56 11.15,59.89 11.15,60.43 11,60.58 10.69,60.58 10.54,60.43 10.54,58.88 10.21,58.55 9.65,58.55 9.32,58.88 9.32,59.41 9.17,59.56 8.76,59.56 J1.17
A13: length 24
  TOP w0.152: J1.18 8.71,59.87 9.3,59.87 9.63,59.54 9.63,59 9.78,58.85 10.08,58.85 10.24,59 10.24,60.55 10.57,60.88 11.13,60.88 11.46,60.55 11.46,60.02 11.61,59.87 13.31,59.87 14.91,58.27 14.91,52.96 15.34,52.53 20.14,52.53 20.32,52.7 21.72,52.7
A14: length 23.8
  TOP w0.152: J1.19 8.76,64.64 13.46,64.64 15.24,62.86 15.24,54.74 15.85,54.13 20.14,54.13 20.29,53.98 21.72,53.98
A15: length 23.7
  TOP w0.152: J1.20 8.71,64.95 13.59,64.95 15.54,62.99 15.54,54.86 15.98,54.43 20.14,54.43 20.32,54.61 21.72,54.61
A16: length 9.2
  TOP w0.127: U1.47 v1(19.02,26.03)
  INNER_2 w0.127: v1(19.02,26.03) 14.6,26.03 J1.37
A17: length 10
  TOP w0.127: U1.46 v1(19.43,26.67)
  BOTTOM w0.127: v1(19.43,26.67) 16.51,26.67 J1.38
A18: length 46.2
  TOP w0.127: U1.44 v1(19.43,27.94)
  INNER_1 w0.127: J1.39 17.78,27.94 v1(19.43,27.94) 22.48,24.89 32.41,24.89 35.33,27.81 35.33,38.51 U2.6
A19: length 61.5
  TOP w0.127: J1.40 11.61,35.56 10.19,34.14 7.65,34.14 6.63,35.15 6.63,43.64 7.44,44.45 8.48,44.45 8.56,44.53 11.76,44.53 11.84,44.45 13.28,44.45 14.55,45.72 U2.5 ; U1.43 v1(19.02,28.58)
  INNER_2 w0.127: J1.40 12.7,34.9 v1(19.02,28.58)
A20: length 62.2
  TOP w0.127: U1.41 v1(19.02,29.84)
  INNER_1 w0.127: v1(19.02,29.84) 18.29,30.58 18.29,32.51 J1.41
  INNER_2 w0.127: J1.41 13.94,39.34 28.57,39.34 33.4,44.17 47.47,44.17 48.62,45.31 48.62,46.2 47.6,47.22 41.05,47.22 U2.4
A21: length 48.9
  TOP w0.127: U1.40 v1(19.43,30.48)
  GND w0.127: J1.42 13.94,39.4 13.94,32.56 16.03,30.48 v1(19.43,30.48)
  INNER_2 w0.127: J1.42 20.19,48.13 23.57,48.13 24.59,47.12 36.32,47.12 U2.3
A22: length 55.8
  TOP w0.127: U2.2 41.25,52.1 41.25,45.49 40.23,44.48 35.46,44.48 34.16,43.18 J1.43 ; U1.38 v1(19.43,31.75)
  INNER_1 w0.127: J1.43 15.11,43.18 20.19,38.1 20.19,32.51 v1(19.43,31.75)
A23: length 50.2
  TOP w0.127: U2.1 40,54.81 31.9,46.71 13.69,46.71 J1.44 ; U1.37 v1(19.02,32.38)
  BOTTOM w0.127: v1(19.02,32.38) 14.2,37.21 14.2,44.22 J1.44
AEN: length 38.9
  TOP w0.127: U2.8 37.44,38.1 34.24,41.3 v1(15.65,41.3)
  BOTTOM w0.127: v1(15.65,41.3) 15.65,50.39 J1.47
BA0: length 87.6
  TOP w0.127: U5.A6 v1(55.91,93.88) ; v1(33.81,33.02) v1(32.13,33.02) U1.13 ; U4.13 v1(32.77,81.28) ; U3.13 v1(29.46,55.24)
  INNER_1 w0.127: v1(55.91,93.88) 55.4,94.39 46.41,94.39 33.3,81.28 v1(32.77,81.28)
  BOTTOM w0.127: v1(33.81,33.02) 33.81,50.9 v1(29.46,55.24) 31.75,57.53 31.75,80.26 v1(32.77,81.28)
BA1: length 92.1
  TOP w0.127: U5.A7 v1(57.18,93.88) ; U3.14 v1(29.06,55.88) ; U1.14 v1(32.54,33.66) ; v1(34.8,55.88) 34.8,80.29 v1(33.17,81.91) U4.14
  INNER_1 w0.127: v1(32.54,33.66) 34.8,35.92 v1(34.8,55.88) ; v1(33.17,81.91) 45.9,94.64 56.41,94.64 v1(57.18,93.88)
  INNER_2 w0.127: v1(34.8,55.88) v1(29.06,55.88)
BA2: length 92
  TOP w0.127: U4.16 v1(33.17,83.19) ; U1.16 v1(32.54,34.92) ; U5.A8 v1(58.45,93.88) ; U3.16 v1(29.06,57.15)
  INNER_1 w0.127: v1(33.17,83.19) 44.88,94.89 57.43,94.89 v1(58.45,93.88)
  VCC w0.127: 33.3,57.15 v1(29.06,57.15) ; 33.3,57.15 33.3,35.69 v1(32.54,34.92) ; 33.3,57.15 33.55,57.15 33.55,59.03 32,60.58 32,82.55 32.64,83.19 v1(33.17,83.19)
BA3: length 89.9
  TOP w0.127: U1.17 v1(32.13,35.56) ; U5.A9 v1(59.72,93.88) ; U3.17 v1(29.46,57.78) ; U4.17 v1(32.77,83.82)
  GND w0.127: v1(32.77,83.82) 38.2,83.82 47.75,93.37 59.21,93.37 v1(59.72,93.88) ; v1(32.13,35.56) 27.03,40.67 27.03,55.85 28.96,57.78 v1(29.46,57.78)
  VCC w0.127: v1(32.77,83.82) 31.24,82.3 31.24,59.56 v1(29.46,57.78)
BA4: length 63.4
  TOP w0.127: U1.19 v1(32.13,36.83) ; U3.19 v1(29.46,59.05) ; U4.19 v1(32.77,85.09)
  INNER_2 w0.127: v1(26.14,36.6) 26.37,36.83 v1(32.13,36.83)
  BOTTOM w0.127: v1(32.77,85.09) 30.23,82.55 30.23,59.82 v1(29.46,59.05) 27.53,59.05 26.14,57.66 v1(26.14,36.6)
BA5: length 61
  TOP w0.127: U4.20 v1(33.17,85.72) ; U1.20 v1(32.54,37.46) ; U3.20 v1(29.06,59.69)
  GND w0.127: v1(29.06,59.69) 30.61,59.69 33.05,57.25 33.05,37.97 v1(32.54,37.46)
  BOTTOM w0.127: v1(29.06,59.69) 26.9,61.85 26.9,80.01 32.61,85.72 v1(33.17,85.72)
BA6: length 67.9
  TOP w0.127: 31.11,87 v1(33.17,87) 33.93,87.76 33.93,88.27 33.17,89.03 30.1,89.03 29.46,88.39 29.46,65.81 28.55,64.9 28.55,61.47 v1(29.06,60.96) U3.22 ; U1.22 v1(32.54,38.73)
  VCC w0.127: v1(32.54,38.73) 33.05,39.24 33.05,40.26 32.79,40.51 28.55,40.51 28.42,40.64 28.42,60.32 v1(29.06,60.96)
BA7: length 55.7
  TOP w0.127: U1.23 v1(32.13,39.37) ; U3.23 v1(29.46,61.59) ; U4.23 v1(32.77,87.63)
  INNER_1 w0.127: v1(32.77,87.63) 30.48,85.34 30.48,62.61 v1(29.46,61.59) 30.84,60.22 30.84,40.67 v1(32.13,39.37)
BD0: length 28.1
  TOP w0.127: U4.12 v1(33.17,80.64) ; U5.C5 v1(53.57,91.34)
  INNER_2 w0.127: v1(53.57,91.34) 53.57,90.58 51.28,88.29 40.82,88.29 v1(33.17,80.64)
BD1: length 28.5
  TOP w0.127: U4.11 v1(32.77,80.01) ; U5.C4 v1(52.3,91.34)
  INNER_1 w0.127: v1(52.3,91.34) 51.79,91.85 51.79,92.61 51.28,93.12 48.18,93.12 35.08,80.01 v1(32.77,80.01)
BD2: length 30.7
  TOP w0.127: U4.9 v1(32.77,78.74) ; U5.C3 v1(51.03,91.34)
  BOTTOM w0.127: v1(51.03,91.34) 50.27,90.58 50.27,82.42 46.58,78.74 v1(32.77,78.74)
BD3: length 32.8
  TOP w0.127: U4.8 v1(33.17,78.11) ; U5.C2 v1(49.76,91.34)
  INNER_2 w0.127: v1(49.76,91.34) 49,90.58 49,89.81 48.74,89.56 33.66,89.56 32.26,88.16 32.26,78.51 32.66,78.11 v1(33.17,78.11)
BD4: length 32.8
  TOP w0.127: U4.6 v1(33.17,76.83) ; U5.C1 v1(48.49,91.34)
  INNER_2 w0.127: v1(33.17,76.83) 32.64,76.83 32,77.47 32,88.29 35.05,91.34 v1(48.49,91.34)
BD5: length 43.6
  TOP w0.127: U5.B10 v1(60.99,92.61) ; U4.5 v1(32.77,76.2)
  BOTTOM w0.127: v1(32.77,76.2) 49.89,76.2 54.08,80.39 54.08,90.22 57,93.14 60.45,93.14 v1(60.99,92.61)
BD6: length 46.8
  TOP w0.127: U4.3 v1(32.77,74.93) ; U5.B9 v1(59.72,92.61)
  INNER_2 w0.127: v1(59.72,92.61) 59.21,93.12 53.37,93.12 53.06,92.81 53.06,92.61 52.3,91.85 35.18,91.85 31.5,88.16 31.5,76.2 v1(32.77,74.93)
BD7: length 40.5
  TOP w0.127: U5.B8 v1(58.45,92.61) ; U4.2 v1(33.17,74.3)
  BOTTOM w0.127: v1(58.45,92.61) 55.12,89.28 55.12,81.03 48.39,74.3 v1(33.17,74.3)
BD8: length 22.1
  TOP w0.127: U3.2 v1(29.06,48.26) ; U1.12 v1(32.54,32.38)
  BOTTOM w0.127: v1(29.06,48.26) 29.57,48.26 31.09,46.74 31.09,33.27 31.98,32.38 v1(32.54,32.38)
BD9: length 22.7
  TOP w0.127: U1.11 v1(32.13,31.75) ; U3.3 v1(29.46,48.89)
  INNER_1 w0.127: v1(29.46,42.32) 28.45,43.33 28.45,48.39 28.96,48.89 v1(29.46,48.89)
  BOTTOM w0.127: v1(29.46,42.32) 29.46,34.42 v1(32.13,31.75)
BD10: length 24.1
  TOP w0.127: U3.5 v1(29.46,50.16) ; U1.9 v1(32.13,30.48)
  INNER_1 w0.127: v1(29.46,50.16) 30.58,49.05 30.58,32.03 v1(32.13,30.48)
BD11: length 28.4
  TOP w0.127: U1.8 v1(32.54,29.84) ; U3.6 v1(29.06,50.8)
  BOTTOM w0.127: v1(32.54,29.84) 31.98,29.84 27.15,34.67 27.15,48.89 v1(29.06,50.8)
BD12: length 29.8
  TOP w0.127: U1.6 v1(32.54,28.58) ; U3.8 v1(29.06,52.07)
  BOTTOM w0.127: v1(32.54,28.58) 33.05,29.08 33.05,48.64 29.62,52.07 v1(29.06,52.07)
BD13: length 30.5
  TOP w0.127: U3.9 v1(29.46,52.7) ; U1.5 v1(32.13,27.94)
  INNER_1 w0.127: v1(29.46,52.7) 28.96,52.7 28.19,51.94 28.19,31.88 v1(32.13,27.94)
BD14: length 34.4
  TOP w0.127: U3.11 v1(29.46,53.98) ; U1.3 v1(32.13,26.67)
  BOTTOM w0.127: v1(29.46,53.98) 28.93,53.98 26.64,51.69 26.64,32.16 v1(32.13,26.67)
BD15: length 35.1
  TOP w0.127: U3.12 v1(29.06,54.61) ; U1.2 v1(32.54,26.03)
  BOTTOM w0.127: v1(32.54,26.03) 33.3,26.8 33.3,50.93 29.62,54.61 v1(29.06,54.61)
BNC2: length 14.4
  TOP w0.127: L1.2 115.57,33.02 J2.1
  INNER_1 w0.127: J2.1 119.38,38.25 v1(120.5,39.37)
  BOTTOM w0.127: C5.1 v1(120.5,39.37)
BNC3: length 13.4
  TOP w0.127: L2.2 116.84,13.97 J3.1
  INNER_1 w0.127: v1(120.5,19.69) 119.38,18.57 J3.1
  BOTTOM w0.127: C6.1 v1(120.5,19.69)
BRD: length 64.1
  TOP w0.127: U5.D9 v1(59.72,90.07)
  BOTTOM w0.127: v1(59.72,90.07) 59.21,90.58 59.21,91.34 58.7,91.85 58.17,91.85 55.37,89.05 55.37,43.31 U2.16
BRESET: length 63.1
  TOP w0.127: U5.B2 v1(49.76,92.61)
  VCC w0.127: v1(49.76,92.61) 50.27,92.1 51.03,92.1 51.54,91.59 51.54,36.93 U2.15
BWR: length 47.5
  TOP w0.127: U5.H2 v1(49.76,83.92)
  INNER_1 w0.127: v1(49.76,83.92) 49.02,83.19 49.02,39.5 U2.17
D0: length 58.6
  TOP w0.127: 21.72,61.59 20.32,61.59 19.81,62.1 19.81,64.9 21.21,66.29 25.4,66.29 27.05,67.95 27.05,83.82 23.24,87.63 19.56,87.63 19.43,87.76 19.1,87.76 18.97,87.88 18.97,88.39 18.85,88.52 18.59,88.52 18.47,88.39 18.47,87.88 18.34,87.76 18.08,87.76 17.96,87.88 17.96,88.39 17.83,88.52 17.58,88.52 17.45,88.39 17.45,87.88 17.32,87.76 17.07,87.76 16.94,87.88 16.94,88.39 16.81,88.52 16.56,88.52 16.43,88.39 16.43,87.88 16.31,87.76 16.05,87.76 15.93,87.88 15.93,88.39 15.8,88.52 15.54,88.52 15.42,88.39 15.42,87.88 15.29,87.76 15.04,87.76 14.91,87.88 14.91,88.39 14.78,88.52 14.53,88.52 14.4,88.39 14.4,87.88 14.27,87.76 11.15,87.76 10.54,87.15 10.39,87.15 9.91,87.63 9.75,87.63 9.52,87.4 9.52,87.25 10.01,86.77 10.01,86.61 9.75,86.36 J1.28
D1: length 60
  TOP w0.127: 21.72,60.96 20.19,60.96 19.56,61.59 19.56,65.02 21.08,66.55 25.27,66.55 26.8,68.07 26.8,83.44 23.24,87 20.29,87 20.17,87.12 20.17,87.25 20.04,87.38 19.79,87.38 19.66,87.25 19.66,87.12 19.53,87 19.28,87 19.15,87.12 19.15,87.25 19.02,87.38 18.77,87.38 18.64,87.25 18.64,87.12 18.52,87 18.26,87 18.14,87.12 18.14,87.25 18.01,87.38 17.75,87.38 17.63,87.25 17.63,87.12 17.5,87 17.25,87 17.12,87.12 17.12,87.25 16.99,87.38 16.74,87.38 16.61,87.25 16.61,87.12 16.48,87 16.23,87 16.1,87.12 16.1,87.25 15.98,87.38 15.72,87.38 15.6,87.25 15.6,87.12 15.47,87 15.21,87 15.09,87.12 15.09,87.25 14.96,87.38 14.71,87.38 14.58,87.25 14.58,87.12 14.45,87 14.1,87 13.59,87.5 11.3,87.5 10.57,86.77 10.57,86.61 11.1,86.08 11.1,85.93 10.87,85.7 10.72,85.7 10.19,86.23 10.03,86.23 9.8,86 9.8,85.85 10.34,85.32 10.34,85.17 10.11,84.94 9.96,84.94 9.42,85.47 9.27,85.47 9.04,85.24 9.04,85.09 9.58,84.56 9.58,84.4 9.35,84.18 9.19,84.18 8.66,84.71 8.51,84.71 J1.27
D2: length 58.5
  TOP w0.127: 21.72,59.69 20.32,59.69 19.3,60.71 19.3,65.15 20.95,66.8 25.15,66.8 26.54,68.2 26.54,82.42 23.24,85.72 19.25,85.72 19.13,85.85 19.13,86.23 19,86.36 18.75,86.36 18.62,86.23 18.62,85.85 18.49,85.72 18.24,85.72 18.11,85.85 18.11,86.23 17.98,86.36 17.73,86.36 17.6,86.23 17.6,85.85 17.48,85.72 17.22,85.72 17.09,85.85 17.09,86.23 16.97,86.36 16.71,86.36 16.59,86.23 16.59,85.85 16.46,85.72 16.21,85.72 16.08,85.85 16.08,86.23 15.95,86.36 15.7,86.36 15.57,86.23 15.57,85.85 15.44,85.72 15.11,85.72 14.6,85.22 11.56,85.22 10.62,84.28 10.46,84.28 10.24,84.51 10.08,84.51 9.86,84.28 9.86,84.12 10.08,83.9 10.08,83.74 9.86,83.52 9.7,83.52 9.47,83.74 9.32,83.74 9.09,83.52 9.09,83.36 9.32,83.13 9.32,82.98 9.09,82.75 8.94,82.75 8.71,82.98 8.56,82.98 8.33,82.75 8.33,82.6 8.56,82.37 8.56,82.22 J1.26
D3: length 58.5
  TOP w0.127: J1.25 9.02,80.14 9.02,80.39 8.89,80.52 8.76,80.52 8.64,80.64 8.64,80.9 8.76,81.03 8.89,81.03 9.02,81.15 9.02,81.66 9.91,82.55 10.19,82.55 10.31,82.68 10.31,82.93 10.44,83.06 10.69,83.06 10.82,82.93 10.82,82.68 10.95,82.55 11.2,82.55 11.33,82.68 11.33,82.93 11.46,83.06 11.71,83.06 11.84,82.93 11.84,82.68 11.96,82.55 13.84,82.55 14.3,83.01 14.3,83.16 14.2,83.26 14.2,83.41 14.43,83.64 14.58,83.64 14.68,83.54 14.83,83.54 15.06,83.77 15.06,83.92 14.96,84.02 14.96,84.18 15.19,84.4 15.34,84.4 15.44,84.3 15.6,84.3 15.82,84.53 15.82,84.68 15.72,84.79 15.72,84.94 15.95,85.17 16.1,85.17 16.21,85.06 16.38,85.09 16.71,85.09 16.84,85.22 16.84,85.34 16.97,85.47 17.22,85.47 17.35,85.34 17.35,85.22 17.48,85.09 17.73,85.09 17.86,85.22 17.86,85.34 17.98,85.47 18.24,85.47 18.36,85.34 18.36,85.22 18.49,85.09 18.75,85.09 18.87,85.22 18.87,85.34 19,85.47 19.25,85.47 19.38,85.34 19.38,85.22 19.51,85.09 23.24,85.09 26.29,82.04 26.29,68.33 25.02,67.06 20.83,67.06 19.05,65.28 19.05,60.32 20.32,59.05 21.72,59.05
D4: length 58.5
  TOP w0.127: 21.72,57.78 20.19,57.78 18.8,59.18 18.8,65.41 20.7,67.31 24.89,67.31 26.04,68.45 26.04,81.03 23.24,83.82 19.08,83.82 18.95,83.95 18.95,84.33 18.82,84.45 18.57,84.45 18.44,84.33 18.44,83.95 18.31,83.82 18.06,83.82 17.93,83.95 17.93,84.33 17.81,84.45 17.55,84.45 17.42,84.33 17.42,83.95 17.3,83.82 17.04,83.82 16.92,83.95 16.92,84.33 16.79,84.45 16.54,84.45 16.41,84.33 16.41,83.95 16.28,83.82 15.75,83.82 14.22,82.3 10.29,82.3 9.52,81.53 9.52,78.11 J1.24
D5: length 58.9
  TOP w0.127: J1.23 10.03,76.07 10.03,78.99 11.3,80.26 13.72,80.26 14.33,80.87 14.33,81.03 14.05,81.31 14.05,81.46 14.27,81.69 14.43,81.69 14.71,81.41 14.86,81.41 15.09,81.64 15.09,81.79 14.81,82.07 14.81,82.22 15.04,82.45 15.19,82.45 15.47,82.17 15.62,82.17 15.85,82.4 15.85,82.55 15.57,82.83 15.57,82.98 15.8,83.21 15.95,83.21 16.23,82.93 16.38,82.93 16.64,83.19 23.24,83.19 25.78,80.64 25.78,68.58 24.76,67.56 20.57,67.56 18.54,65.53 18.54,58.8 20.19,57.15 21.72,57.15
D6: length 59.1
  TOP w0.127: J1.22 10.41,73.91 10.41,78.74 11.68,80.01 14.1,80.01 16,81.91 16.38,81.91 16.51,82.04 16.51,82.3 16.64,82.42 16.89,82.42 17.02,82.3 17.02,82.04 17.14,81.91 17.4,81.91 17.53,82.04 17.53,82.3 17.65,82.42 17.91,82.42 18.03,82.3 18.03,82.04 18.16,81.91 23.24,81.91 25.53,79.63 25.53,68.71 24.64,67.82 20.45,67.82 18.29,65.66 18.29,57.78 20.19,55.88 21.72,55.88
D7: length 59.6
  TOP w0.127: 21.72,55.24 20.19,55.24 18.03,57.4 18.03,65.79 20.32,68.07 24.51,68.07 25.27,68.83 25.27,79.38 23.37,81.28 15.87,81.28 14.35,79.76 12.06,79.76 10.79,78.49 10.79,71.75 J1.21
D8: length 23.9
  TOP w0.152: U1.36 19.66,33.02 19.51,33.17 15.6,33.17 14.1,31.67 14.1,27.15 13.39,26.49 11.33,26.49 11,26.82 11,27.69 10.85,27.84 10.54,27.84 10.39,27.69 10.39,25.48 10.06,25.15 9.5,25.15 9.17,25.48 9.17,26.34 9.02,26.49 8.71,26.49 J1.4
D9: length 23.9
  TOP w0.152: J1.5 8.76,26.8 9.14,26.8 9.47,26.47 9.47,25.6 9.63,25.45 9.93,25.45 10.08,25.6 10.08,27.81 10.41,28.14 10.97,28.14 11.3,27.81 11.3,26.95 11.46,26.8 13.26,26.8 13.79,27.3 13.79,31.8 15.47,33.48 19.51,33.48 19.68,33.66 U1.35
D10: length 23.9
  TOP w0.152: J1.6 8.76,31.62 9.07,31.62 9.22,31.47 9.22,29.92 9.55,29.59 10.11,29.59 10.44,29.92 10.44,33.5 10.59,33.66 10.9,33.66 11.05,33.5 11.05,31.95 11.38,31.62 13.21,31.62 14,32.41 14,34.44 14.63,35.08 19.51,35.08 19.66,34.92 U1.33
D11: length 23.9
  TOP w0.152: U1.32 19.68,35.56 19.51,35.38 14.5,35.38 13.69,34.57 13.69,32.54 13.08,31.93 11.51,31.93 11.35,32.08 11.35,33.63 11.02,33.96 10.46,33.96 10.13,33.63 10.13,30.05 9.98,29.9 9.68,29.9 9.52,30.05 9.52,31.6 9.19,31.93 8.71,31.93 J1.7
D12: length 23.8
  TOP w0.152: U1.30 19.66,36.83 19.51,36.98 17.04,36.98 16.71,37.31 16.71,37.49 16.56,37.64 16.26,37.64 16.1,37.49 16.1,36.65 15.77,36.32 15.21,36.32 14.88,36.65 14.88,36.83 14.73,36.98 13.87,36.98 13.49,36.6 11.28,36.6 10.95,36.93 10.95,38.63 10.79,38.79 10.49,38.79 10.34,38.63 10.34,34.75 10.01,34.42 9.45,34.42 9.12,34.75 9.12,36.45 8.97,36.6 8.66,36.6 J1.8
D13: length 23.9
  TOP w0.152: J1.9 8.81,36.91 9.09,36.91 9.42,36.58 9.42,34.87 9.58,34.72 9.88,34.72 10.03,34.87 10.03,38.76 10.36,39.09 10.92,39.09 11.25,38.76 11.25,37.06 11.4,36.91 13.36,36.91 13.74,37.29 14.86,37.29 15.19,36.96 15.19,36.78 15.34,36.63 15.65,36.63 15.8,36.78 15.8,37.62 16.13,37.95 16.69,37.95 17.02,37.62 17.02,37.44 17.17,37.29 19.51,37.29 19.68,37.46 U1.29
D14: length 24
  TOP w0.152: J1.10 8.76,41.78 9.07,41.78 9.22,41.63 9.22,39.95 9.55,39.62 10.11,39.62 10.44,39.95 10.44,43.79 10.59,43.94 10.9,43.94 11.05,43.79 11.05,42.11 11.38,41.78 13.33,41.78 13.72,41.4 13.72,39.75 14.58,38.89 19.51,38.89 19.66,38.73 U1.27
D15: length 23.9
  TOP w0.152: U1.26 19.68,39.37 19.51,39.19 14.71,39.19 14.02,39.88 14.02,41.53 13.46,42.09 11.51,42.09 11.35,42.24 11.35,43.92 11.02,44.25 10.46,44.25 10.13,43.92 10.13,40.08 9.98,39.93 9.68,39.93 9.52,40.08 9.52,41.76 9.19,42.09 8.71,42.09 J1.11
DATA: length 24
  TOP w0.127: U5.B4 v1(52.3,92.61)
  INNER_2 w0.127: v1(52.3,92.61) 51.54,93.37 31.09,93.37 U7.1
DCLK: length 33.3
  TOP w0.203: U7.2 57.71,97.16 v1(60.99,93.88) U5.A10
DDIR: length 81.3
  TOP w0.127: U3.48 v1(23.37,47.62) ; U1.48 v1(19.43,25.4) ; U4.48 v1(20.07,73.66)
  INNER_1 w0.127: v1(23.37,47.62) 20.07,50.93 v1(20.07,73.66)
  INNER_2 w0.127: v1(23.37,47.62) 24.28,46.71 46.63,46.71 U2.20
  BOTTOM w0.127: v1(23.37,47.62) 21.21,45.47 21.21,27.18 v1(19.43,25.4)
DEN: length 68.1
  TOP w0.127: U4.1 v1(32.77,73.66) ; U1.1 v1(32.13,25.4)
  BOTTOM w0.127: v1(32.77,73.66) 44.93,61.49 44.93,50.95 U2.21 46.63,47.27 46.63,33.15 38.89,25.4 v1(32.13,25.4)
DHEN: length 21.9
  TOP w0.127: U3.1 v1(29.46,47.62)
  INNER_2 w0.127: U2.22 46.63,51.79 33.63,51.79 v1(29.46,47.62)
FPGA: length 63.7
  TOP w0.127: U5.C10 v1(60.99,91.34)
  INNER_1 w0.127: v1(60.99,91.34) 60.22,90.58 60.22,88.52 59.21,87.5 48.72,87.5 47.96,86.74 47.96,59.54 48.62,58.88 48.62,41.63 U2.18
GAIN: length 92.9
  TOP w0.127: U5.C8 v1(58.45,91.34) ; U23.6 v1(96.44,19.05) ; U19.6 v1(96.44,38.73)
  BOTTOM w0.127: v1(58.45,91.34) 57.68,90.58 57.68,77.5 v1(96.44,38.73) 95.68,37.97 95.68,19.81 v1(96.44,19.05)
HS: length 59.5
  TOP w0.127: U5.C9 v1(59.72,91.34)
  INNER_1 w0.127: v1(59.72,91.34) 56.46,88.09 48.89,88.09 46.23,85.42 46.23,44.58 U2.19
MCLK: length 43.4
  TOP w0.203: U5.J1 v1(48.49,82.65)
  INNER_2 w0.203: J1.52 31.88,66.04 v1(48.49,82.65)
MRD: length 46
  INNER_2 w0.127: J1.46 11.46,49.56 11.46,37.92 12.27,37.11 27.94,37.11 31.6,40.77 34.8,40.77 U2.9
MWR: length 56.4
  INNER_1 w0.127: U2.10 40,32.03 32.38,24.41 12.22,24.41 11.71,24.92 11.71,47.27 J1.45
N00036_12287: length 38.8
  TOP w0.127: U23.5 v1(96.44,20.32) ; U21.8 v1(90.35,17.78) ; L6.2 105.89,8.25 v1(102.72,11.43) v1(102.72,13.97) 102.21,14.48 90.86,14.48 v1(90.35,13.97) U21.5
  INNER_1 w0.127: v1(90.35,17.78) 91.11,17.02 91.11,14.73 v1(90.35,13.97)
  INNER_2 w0.127: v1(96.44,20.32) 92.89,20.32 v1(90.35,17.78)
  BOTTOM w0.127: R17.1 v1(102.72,13.97) ; R18.1 v1(102.72,11.43)
N00038_12290: length 28.9
  TOP w0.127: U21.4 v1(90.35,12.7)
  INNER_2 w0.127: L5.2 99.06,12.7 v1(90.35,12.7) 85.93,12.7 v1(84.45,11.23)
  BOTTOM w0.127: C27.1 v1(84.45,11.23)
N00044_12288: length 23
  TOP w0.127: U23.1 v1(104.32,16.51)
  BOTTOM w0.127: v1(104.32,16.51) 111.66,23.85 U22.2
N00060_12289: length 37.1
  TOP w0.127: U21.6 v1(90.35,15.24) 100.13,25.02 100.13,29.95 102.16,31.98 110.06,31.98 112.73,34.65 112.73,36.5 U22.3
N282866_12286: length 5.8
  TOP w0.127: U23.8 v1(96.44,16.51)
  INNER_1 w0.127: v1(98.17,13.97) 96.44,15.7 v1(96.44,16.51)
  BOTTOM w0.127: R17.2 v1(98.17,13.97)
N282912_12285: length 11.5
  TOP w0.127: U23.2 v1(104.32,17.78)
  INNER_1 w0.127: v1(98.17,11.43) 98.17,11.63 v1(104.32,17.78)
  BOTTOM w0.127: R18.2 v1(98.17,11.43)
NCS: length 30
  TOP w0.127: U5.B1 v1(48.49,92.61)
  INNER_2 w0.127: v1(48.49,92.61) 29.97,92.61 28.57,94.01 28.57,100.97 29.84,102.23
OE: length 30
  TOP w0.127: U5.J2 v1(49.76,82.65)
  BOTTOM w0.127: 29.84,99.69 36.53,99.69 49.23,87 49.23,83.19 v1(49.76,82.65)
OUTA: length 13.3
  INNER_1 w0.127: L1.1 108.69,28.47 U20.6
OUTB: length 29.7
  INNER_1 w0.127: L2.1 105.18,12.93 105.18,36.86 106.96,38.63 U22.6
Q0: length 7.3
  TOP w0.127: U6.12 R4.1
Q1: length 32
  TOP w0.127: R4.2 D4.2
Q2: length 7.3
  TOP w0.127: U6.14 R3.1
Q3: length 25
  TOP w0.127: R3.2 D3.2
Q4: length 7.3
  TOP w0.127: U6.16 R2.1
Q5: length 18
  TOP w0.127: R2.2 D2.2
Q6: length 7.3
  TOP w0.127: U6.18 R1.1
Q7: length 10.4
  TOP w0.127: R1.2 D1.2
RA0: length 149.2
  TOP w0.127: U15.5 81.91,102.64 v1(81.56,103) ; U12.5 106.68,64.47 106.17,64.97 106.17,72.97 106.68,73.48 U16.5 106.68,81.15 107.31,81.79 107.31,85.57 106.68,86.21 U17.5 106.68,92.2 106.17,92.71 106.17,98.6 106.68,99.11 U11.5 v1(106.68,101.78) ; U5.H6 v1(55.91,83.92) ; U10.5 81.91,64.72 82.42,65.23 82.42,72.97 81.91,73.48 U14.5 81.91,80.52 82.42,81.03 82.42,86.36 82.55,86.49 82.55,88.77 82.42,88.9 v1(82.42,90.7) ; U13.5 v1(81.91,89.84)
  INNER_1 w0.127: v1(81.91,89.84) 81.91,90.2 v1(82.42,90.7)
  INNER_2 w0.127: v1(106.68,101.78) 105.46,103 v1(81.56,103) ; v1(82.42,90.7) 59.59,90.7 55.91,87.02 v1(55.91,83.92)
  BOTTOM w0.127: v1(81.91,89.84) 83.69,91.62 83.69,101.98 82.68,103 v1(81.56,103)
RA1: length 140.8
  TOP w0.127: v1(80.64,101.98) 80.64,100.33 ; v1(80.67,89.99) 80.64,89.97 80.64,87.63 ; U5.H8 v1(58.45,83.92) ; v1(80.64,60.71) 80.64,67.01 81.28,67.64 81.28,72.85 80.64,73.48 80.64,80.9 v1(80.14,81.41) ; U11.4 105.41,98.88 105.92,98.37 105.92,93.83 105.41,93.32 U17.4 105.41,86.18 106.04,85.55 106.04,83.31 105.92,83.19 105.92,78.92 105.41,78.41 U16.4 105.41,73.48 105.92,72.97 105.92,64.72 105.41,64.21 U12.4 v1(105.41,60.78)
  INNER_1 w0.127: v1(80.64,60.71) 81.03,61.09 105.11,61.09 v1(105.41,60.78) ; v1(80.14,81.41) 80.14,89.46 v1(80.67,89.99) ; v1(58.45,83.92) 58.98,84.45 58.98,86.46 59.49,86.97 72.95,86.97 v1(75.97,89.99)
  INNER_2 w0.127: v1(75.97,89.99) v1(80.67,89.99)
  BOTTOM w0.127: v1(80.64,101.98) 75.97,97.31 v1(75.97,89.99)
RA2: length 130.8
  TOP w0.127: U5.H9 v1(59.72,83.92) ; v1(104.14,60.58) U12.3 104.14,65.23 104.78,65.86 104.78,72.85 104.14,73.48 U16.3 104.14,78.94 104.78,79.58 104.78,85.55 104.14,86.18 U17.3 104.14,90.12 104.65,90.63 104.65,95.89 104.78,96.01 104.78,98.25 104.14,98.88 U11.3 ; v1(79.38,60.78) U10.3 79.38,64.97 78.87,65.48 78.87,72.97 79.38,73.48 U14.3 79.38,81.74 80.01,82.37 80.01,85.55 79.38,86.18 U13.3 79.38,89.05 v1(79.4,89.08) 79.88,89.56 79.88,95.89 80.01,96.01 80.01,98.25 79.38,98.88 U15.3
  INNER_1 w0.127: v1(59.72,83.92) 60.48,84.68 76.12,84.68 79.4,87.96 v1(79.4,89.08)
  INNER_2 w0.127: v1(104.14,60.58) 103.5,61.21 79.81,61.21 v1(79.38,60.78)
RA3: length 129.4
  TOP w0.127: U5.H10 v1(60.99,83.92) ; v1(78.1,60.78) 78.1,65.99 78.61,66.5 78.61,72.97 78.1,73.48 78.1,76.15 78.74,76.78 78.74,85.55 78.1,86.18 78.1,89.28 v1(78.13,89.31) 78.61,89.79 78.61,95.89 78.74,96.01 78.74,98.25 78.1,98.88 78.1,100.33 ; U11.2 102.87,98.91 103.5,98.27 103.5,93.55 102.87,92.91 U17.2 102.87,86.18 103.5,85.55 103.5,83.31 103.38,83.19 103.38,77.93 102.87,77.42 U16.2 102.87,73.48 103.5,72.85 103.5,68.91 102.87,68.28 U12.2 v1(102.87,60.58)
  INNER_1 w0.127: v1(78.1,60.78) 78.69,60.2 80.85,60.2 81.48,60.83 102.62,60.83 v1(102.87,60.58)
  BOTTOM w0.127: v1(60.99,83.92) 75.36,83.92 78.13,86.69 v1(78.13,89.31)
RA4: length 127.1
  TOP w0.127: U15.32 76.84,106.68 v1(77.19,106.32) ; U11.32 101.6,107.21 v1(100.71,106.32) 100.71,99.52 101.6,98.63 U17.32 101.6,91.39 102.11,90.88 102.11,86.18 101.6,85.67 U16.32 101.6,80.26 100.84,79.5 100.84,73.99 101.6,73.23 U12.32 ; U5.G8 v1(58.45,85.19) ; v1(76.84,86.11) U14.32 76.84,82.4 75.72,81.28 75.72,74.35 76.84,73.23 U10.32 ; v1(76.61,92.61) 76.84,92.84 U13.32
  INNER_1 w0.127: v1(76.61,92.61) 77.19,93.19 v1(77.19,106.32)
  INNER_2 w0.127: v1(58.45,85.19) 59,85.19 59.54,85.72 76.45,85.72 v1(76.84,86.11) ; v1(77.19,106.32) v1(100.71,106.32)
  BOTTOM w0.127: v1(76.84,86.11) 76.84,92.38 v1(76.61,92.61)
RA5: length 131.3
  TOP w0.127: 78.1,109.86 78.1,105.87 77.47,105.23 77.47,99.01 78.1,98.37 78.1,91.85 77.47,91.21 77.47,86.31 78.1,85.67 v1(78.1,81.91) ; U11.31 102.87,107.39 102.23,106.76 102.23,99.03 102.87,98.4 U17.31 102.87,94.79 102.36,94.28 102.36,86.18 102.87,85.67 U16.31 102.87,79.71 102.23,79.07 102.23,73.61 102.87,72.97 U12.31 102.87,71.42 v1(100.43,68.99) ; 78.1,71.75 v1(78.1,69.42) ; U5.G9 v1(59.72,85.19)
  INNER_1 w0.127: v1(78.1,69.42) v1(78.1,81.91)
  INNER_2 w0.127: v1(100.43,68.99) 82.5,68.99 81.31,70.18 78.87,70.18 v1(78.1,69.42) ; v1(59.72,85.19) 60.48,84.43 60.48,83.67 60.99,83.16 76.86,83.16 v1(78.1,81.91)
RA6: length 135.6
  TOP w0.127: U15.30 79.38,108.43 78.74,107.8 78.74,99.01 79.38,98.37 U13.30 79.38,91.11 78.87,90.6 78.87,88.9 78.74,88.77 78.74,86.31 79.38,85.67 U14.30 v1(79.38,82.8) ; U11.30 104.14,108.08 103.5,107.44 103.5,99.01 104.14,98.37 U17.30 104.14,92.15 103.5,91.52 103.5,86.31 104.14,85.67 U16.30 104.14,82.83 103.63,82.32 103.63,76.2 103.5,76.07 103.5,73.61 104.14,72.97 U12.30 v1(104.14,68.71) ; v1(80.14,67.51) 79.38,68.28 U10.30 ; U5.G10 v1(60.99,85.19)
  INNER_1 w0.127: v1(79.38,82.8) 79.38,68.28 v1(80.14,67.51)
  INNER_2 w0.127: v1(80.14,67.51) 102.95,67.51 v1(104.14,68.71) ; v1(60.99,85.19) 76.99,85.19 v1(79.38,82.8)
RA7: length 137.2
  TOP w0.127: 57.91,87 v1(58.45,86.46) ; v1(105.41,70.26) U12.29 105.41,72.97 104.78,73.61 104.78,79.04 105.41,79.68 U16.29 105.41,85.67 104.78,86.31 104.78,88.77 104.9,88.9 104.9,93.68 105.41,94.18 U17.29 105.41,98.37 104.78,99.01 104.78,107.04 105.41,107.67 U11.29 ; 80.64,109.86 80.64,102.9 81.28,102.26 81.28,99.26 80.64,98.63 80.64,90.75 80.14,90.25 80.14,88.9 80.01,88.77 80.01,86.56 80.39,86.18 v1(80.64,86.18) 80.64,84.45 ; 80.64,71.75 v1(80.64,68.99)
  INNER_1 w0.127: v1(80.64,86.18) v1(80.64,68.99)
  INNER_2 w0.127: v1(80.64,86.18) 79.86,86.97 58.95,86.97 v1(58.45,86.46)
  BOTTOM w0.127: v1(80.64,68.99) 81.46,68.17 100.53,68.17 102.62,70.26 v1(105.41,70.26)
